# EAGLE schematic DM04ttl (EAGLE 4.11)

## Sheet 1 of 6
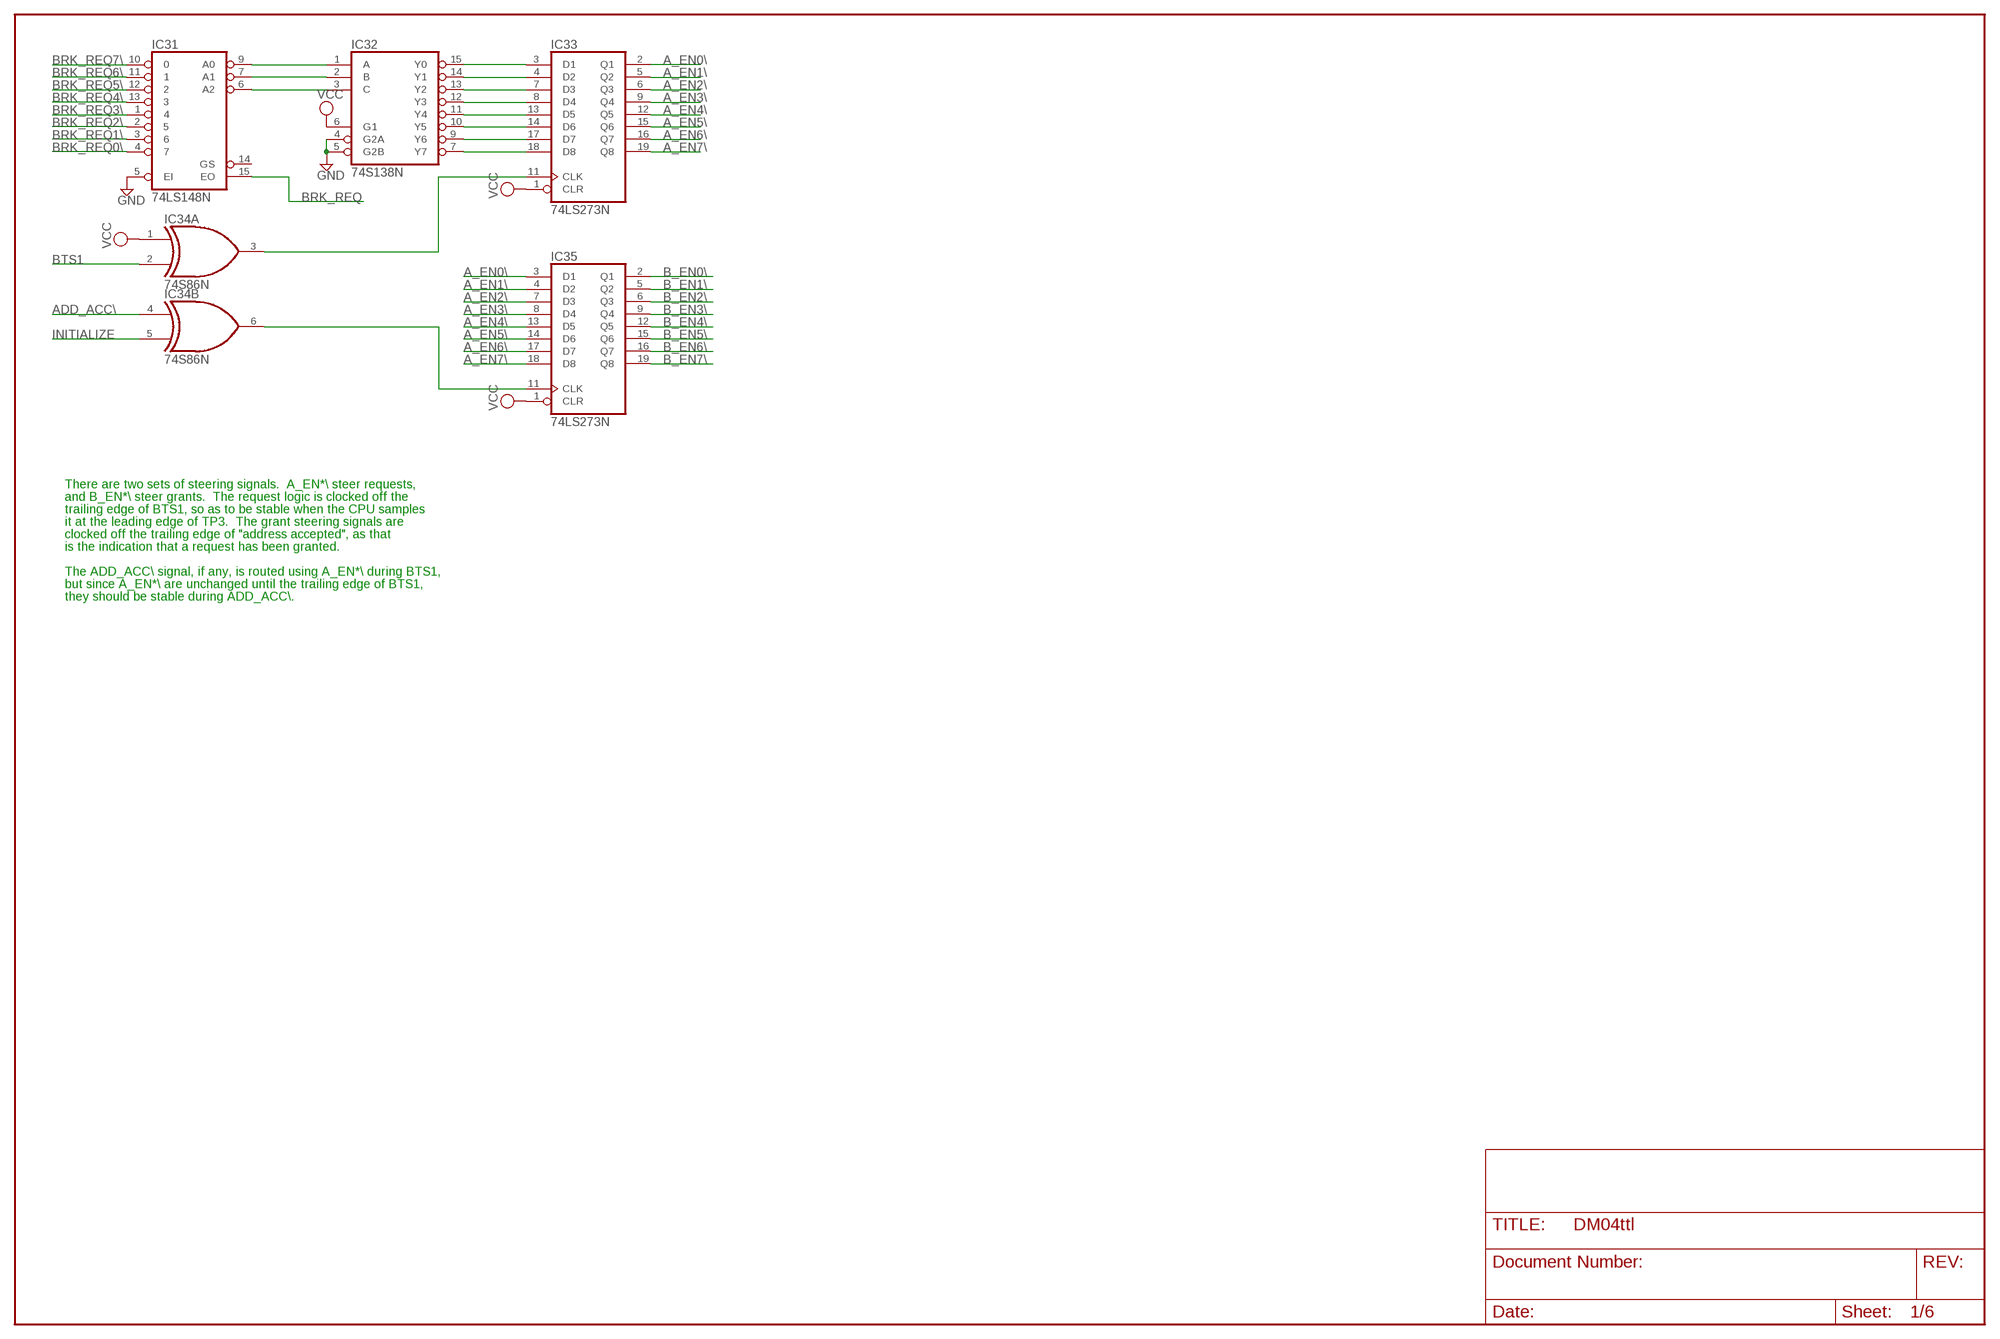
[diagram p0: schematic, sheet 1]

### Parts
IC31  74LS148N  [DIL16]
IC32  74S138N  [DIL16]
IC33  74LS273N  [DIL20]
IC34  74S86N  [DIL14]
IC35  74LS273N  [DIL20]

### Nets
A_EN0\: IC33.2(Q1) IC35.3(D1) ; also sheet 4,6
A_EN1\: IC33.5(Q2) IC35.4(D2) ; also sheet 4,6
A_EN2\: IC33.6(Q3) IC35.7(D3) ; also sheet 4,6
A_EN3\: IC33.9(Q4) IC35.8(D4) ; also sheet 4,6
A_EN4\: IC33.12(Q5) IC35.13(D5) ; also sheet 3
A_EN5\: IC33.15(Q6) IC35.14(D6) ; also sheet 3
A_EN6\: IC33.16(Q7) IC35.17(D7) ; also sheet 3
A_EN7\: IC33.19(Q8) IC35.18(D8) ; also sheet 3
ADD_ACC\: IC34.4(B:I0) ; also sheet 3,6
B_EN0\: IC35.2(Q1) ; also sheet 5,6
B_EN1\: IC35.5(Q2) ; also sheet 5,6
B_EN2\: IC35.6(Q3) ; also sheet 5,6
B_EN3\: IC35.9(Q4) ; also sheet 5,6
B_EN4\: IC35.12(Q5) ; also sheet 3
B_EN5\: IC35.15(Q6) ; also sheet 3
B_EN6\: IC35.16(Q7) ; also sheet 3
B_EN7\: IC35.19(Q8) ; also sheet 3
BRK_REQ: IC31.15(EO) ; also sheet 5
BRK_REQ0\: IC31.4 ; also sheet 3
BRK_REQ1\: IC31.3 ; also sheet 3
BRK_REQ2\: IC31.2 ; also sheet 3
BRK_REQ3\: IC31.1 ; also sheet 3
BRK_REQ4\: IC31.13 ; also sheet 3
BRK_REQ5\: IC31.12 ; also sheet 3
BRK_REQ6\: IC31.11 ; also sheet 3
BRK_REQ7\: IC31.10 ; also sheet 3
BTS1: IC34.2(A:I1) ; also sheet 2
GND [Supply]: IC31.5(EI) IC32.4(G2A) IC32.5(G2B) ; also sheet 2,3,4,5,6
INITIALIZE: IC34.5(B:I1) ; also sheet 3
N$2: IC31.6(A2) IC32.3(C)
N$3: IC34.6(B:O) IC35.11(CLK)
N$6: IC31.7(A1) IC32.2(B)
N$8: IC31.9(A0) IC32.1(A)
N$12: IC32.15(Y0) IC33.3(D1)
N$14: IC32.7(Y7) IC33.18(D8)
N$16: IC32.9(Y6) IC33.17(D7)
N$18: IC32.10(Y5) IC33.14(D6)
N$20: IC32.11(Y4) IC33.13(D5)
N$22: IC32.12(Y3) IC33.8(D4)
N$24: IC32.13(Y2) IC33.7(D3)
N$26: IC32.14(Y1) IC33.4(D2)
N$27: IC33.11(CLK) IC34.3(A:O)
VCC [Supply]: IC32.6(G1) IC33.1(CLR) IC34.1(A:I0) IC35.1(CLR) ; also sheet 2,3
Unconnected: IC31.14(GS) IC34.8(C:O) IC34.9(C:I0) IC34.10(C:I1) IC34.11(D:O) IC34.12(D:I0) IC34.13(D:I1)

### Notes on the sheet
- There are two sets of steering signals.  A_EN*\ steer requests,
- and B_EN*\ steer grants.  The request logic is clocked off the
- trailing edge of BTS1, so as to be stable when the CPU samples
- it at the leading edge of TP3.  The grant steering signals are
- clocked off the trailing edge of "address accepted", as that
- is the indication that a request has been granted.
- The ADD_ACC\ signal, if any, is routed using A_EN*\ during BTS1,
- but since A_EN*\ are unchanged until the trailing edge of BTS1,
- they should be stable during ADD_ACC\.

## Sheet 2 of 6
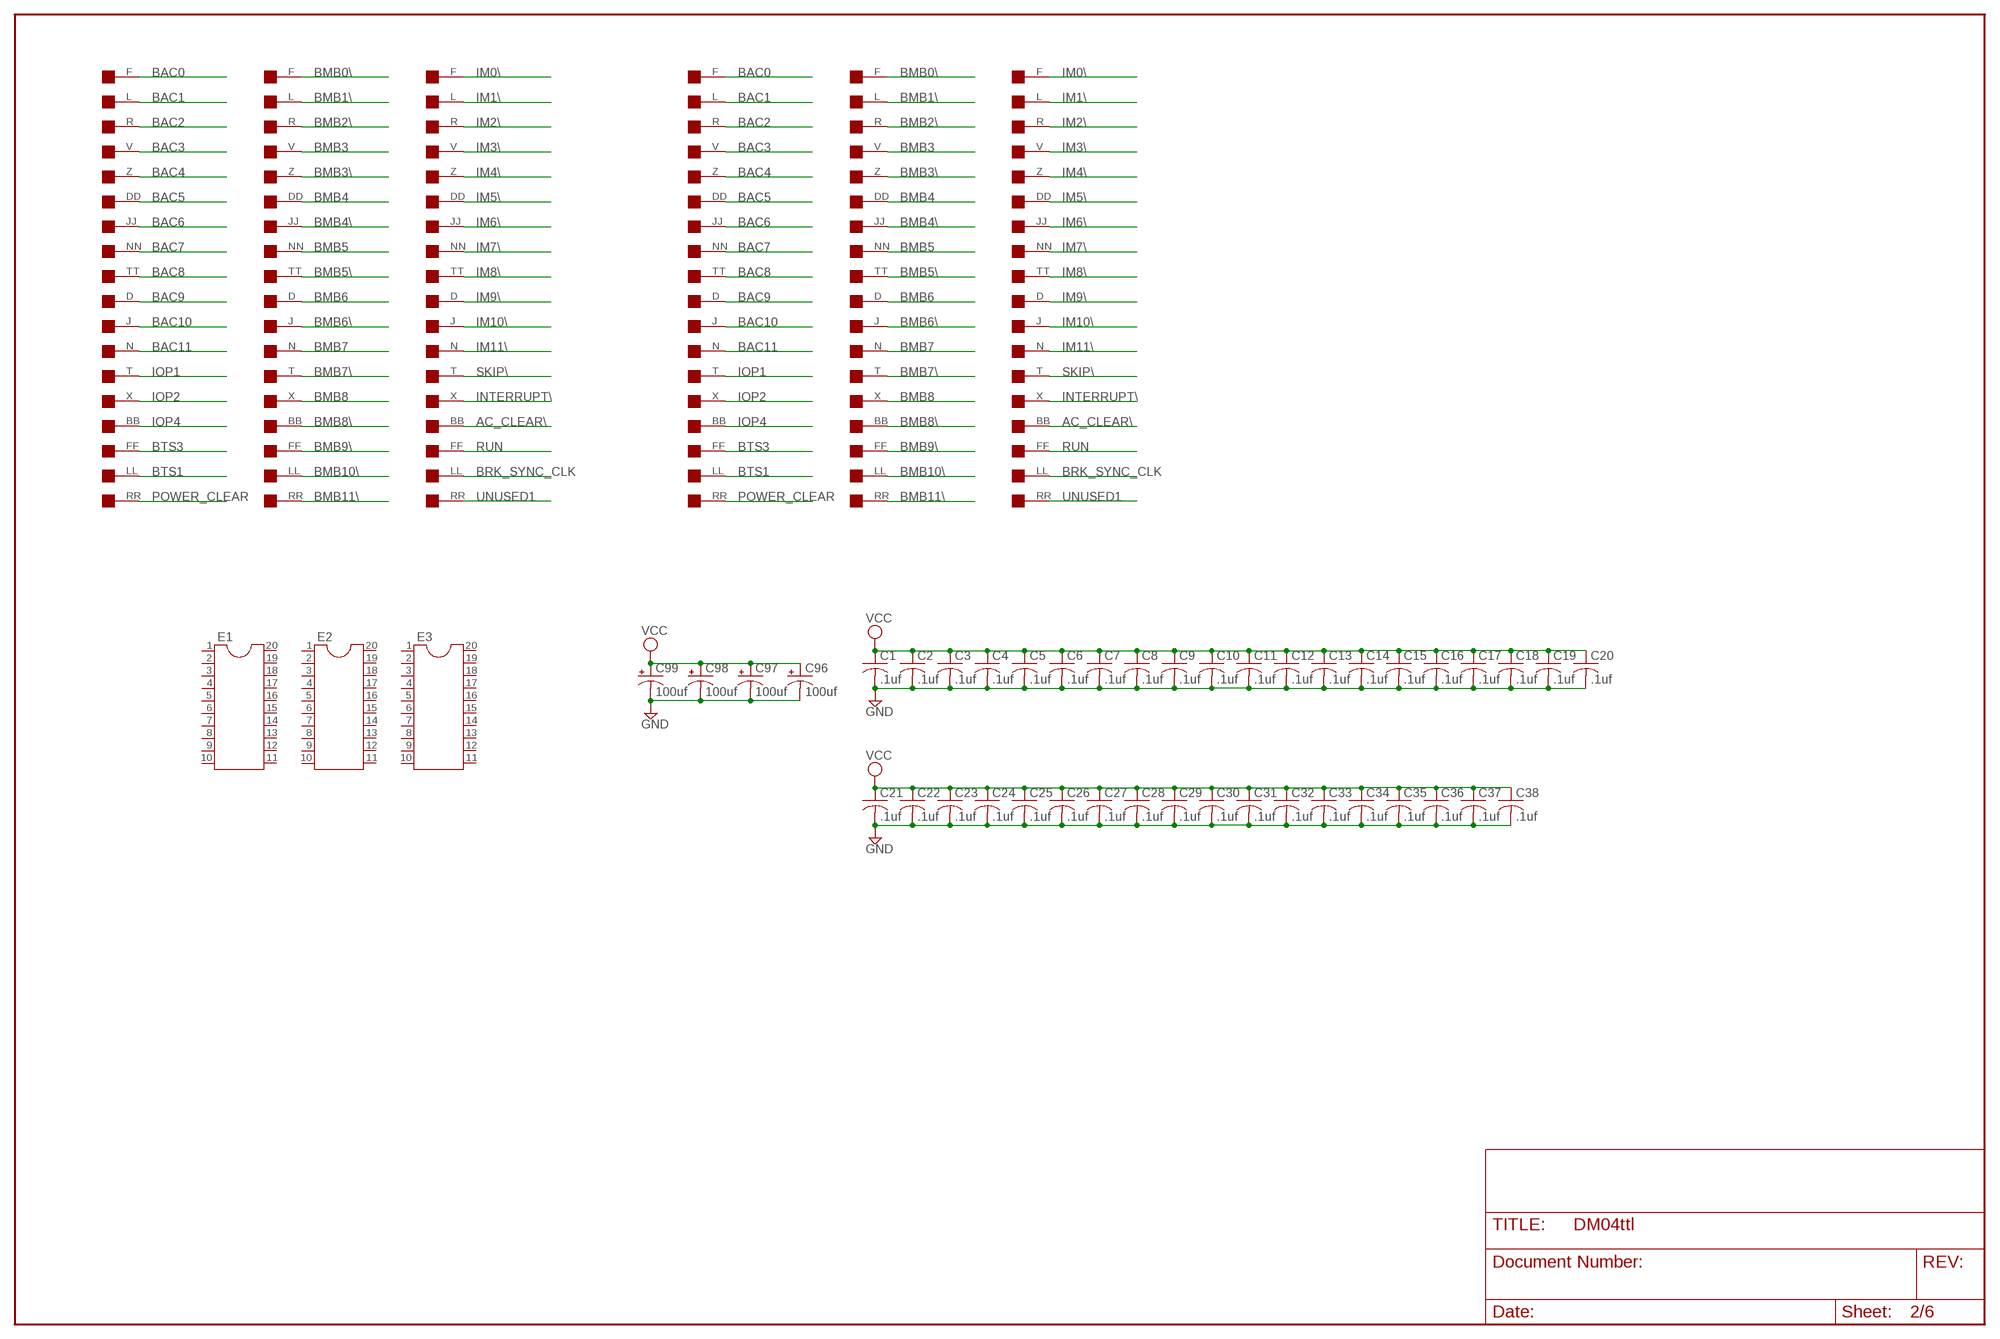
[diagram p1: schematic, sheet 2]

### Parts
AC0  BC08J  [DEC40PINV]
AC1  BC08J  [DEC40PINV]
BAC0  BC08J  [DEC40PINV]
BAC1  BC08J  [DEC40PINV]
BMB0  BC08J  [DEC40PINV]
BMB1  BC08J  [DEC40PINV]
C1  .1uf  C-US050-025X075  [C050-025X075]
C2  .1uf  C-US050-025X075  [C050-025X075]
C3  .1uf  C-US050-025X075  [C050-025X075]
C4  .1uf  C-US050-025X075  [C050-025X075]
C5  .1uf  C-US050-025X075  [C050-025X075]
C6  .1uf  C-US050-025X075  [C050-025X075]
C7  .1uf  C-US050-025X075  [C050-025X075]
C8  .1uf  C-US050-025X075  [C050-025X075]
C9  .1uf  C-US050-025X075  [C050-025X075]
C10  .1uf  C-US050-025X075  [C050-025X075]
C11  .1uf  C-US050-025X075  [C050-025X075]
C12  .1uf  C-US050-025X075  [C050-025X075]
C13  .1uf  C-US050-025X075  [C050-025X075]
C14  .1uf  C-US050-025X075  [C050-025X075]
C15  .1uf  C-US050-025X075  [C050-025X075]
C16  .1uf  C-US050-025X075  [C050-025X075]
C17  .1uf  C-US050-025X075  [C050-025X075]
C18  .1uf  C-US050-025X075  [C050-025X075]
C19  .1uf  C-US050-025X075  [C050-025X075]
C20  .1uf  C-US050-025X075  [C050-025X075]
C21  .1uf  C-US050-025X075  [C050-025X075]
C22  .1uf  C-US050-025X075  [C050-025X075]
C23  .1uf  C-US050-025X075  [C050-025X075]
C24  .1uf  C-US050-025X075  [C050-025X075]
C25  .1uf  C-US050-025X075  [C050-025X075]
C26  .1uf  C-US050-025X075  [C050-025X075]
C27  .1uf  C-US050-025X075  [C050-025X075]
C28  .1uf  C-US050-025X075  [C050-025X075]
C29  .1uf  C-US050-025X075  [C050-025X075]
C30  .1uf  C-US050-025X075  [C050-025X075]
C31  .1uf  C-US050-025X075  [C050-025X075]
C32  .1uf  C-US050-025X075  [C050-025X075]
C33  .1uf  C-US050-025X075  [C050-025X075]
C34  .1uf  C-US050-025X075  [C050-025X075]
C35  .1uf  C-US050-025X075  [C050-025X075]
C36  .1uf  C-US050-025X075  [C050-025X075]
C37  .1uf  C-US050-025X075  [C050-025X075]
C38  .1uf  C-US050-025X075  [C050-025X075]
C96  100uf  CPOL-USE22-6AXIAL  [E22-6]
C97  100uf  CPOL-USE22-6AXIAL  [E22-6]
C98  100uf  CPOL-USE22-6AXIAL  [E22-6]
C99  100uf  CPOL-USE22-6AXIAL  [E22-6]
E1  DIL20  [DIL20]
E2  DIL20  [DIL20]
E3  DIL20  [DIL20]

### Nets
AC_CLEAR\: AC0.BB AC1.BB
BAC0: BAC0.F BAC1.F
BAC1: BAC0.L BAC1.L
BAC2: BAC0.R BAC1.R
BAC3: BAC0.V BAC1.V
BAC4: BAC0.Z BAC1.Z
BAC5: BAC0.DD BAC1.DD
BAC6: BAC0.JJ BAC1.JJ
BAC7: BAC0.NN BAC1.NN
BAC8: BAC0.TT BAC1.TT
BAC9: BAC0.D BAC1.D
BAC10: BAC0.J BAC1.J
BAC11: BAC0.N BAC1.N
BMB0\: BMB0.F BMB1.F
BMB1\: BMB0.L BMB1.L
BMB2\: BMB0.R BMB1.R
BMB3: BMB0.V BMB1.V
BMB3\: BMB0.Z BMB1.Z
BMB4: BMB0.DD BMB1.DD
BMB4\: BMB0.JJ BMB1.JJ
BMB5: BMB0.NN BMB1.NN
BMB5\: BMB0.TT BMB1.TT
BMB6: BMB0.D BMB1.D
BMB6\: BMB0.J BMB1.J
BMB7: BMB0.N BMB1.N
BMB7\: BMB0.T BMB1.T
BMB8: BMB0.X BMB1.X
BMB8\: BMB0.BB BMB1.BB
BMB9\: BMB0.FF BMB1.FF
BMB10\: BMB0.LL BMB1.LL
BMB11\: BMB0.RR BMB1.RR
BRK_SYNC_CLK: AC0.LL AC1.LL
BTS1: BAC0.LL BAC1.LL ; also sheet 1
BTS3: BAC0.FF BAC1.FF
GND [Supply]: C1.2 C2.2 C3.2 C4.2 C5.2 C6.2 C7.2 C8.2 C9.2 C10.2 C11.2 C12.2 C13.2 C14.2 C15.2 C16.2 C17.2 C18.2 C19.2 C20.2 C21.2 C22.2 C23.2 C24.2 C25.2 C26.2 C27.2 C28.2 C29.2 C30.2 C31.2 C32.2 C33.2 C34.2 C35.2 C36.2 C37.2 C38.2 C96.- C97.- C98.- C99.- ; also sheet 1,3,4,5,6
IM0\: AC0.F AC1.F
IM1\: AC0.L AC1.L
IM2\: AC0.R AC1.R
IM3\: AC0.V AC1.V
IM4\: AC0.Z AC1.Z
IM5\: AC0.DD AC1.DD
IM6\: AC0.JJ AC1.JJ
IM7\: AC0.NN AC1.NN
IM8\: AC0.TT AC1.TT
IM9\: AC0.D AC1.D
IM10\: AC0.J AC1.J
IM11\: AC0.N AC1.N
INTERRUPT\: AC0.X AC1.X
IOP1: BAC0.T BAC1.T
IOP2: BAC0.X BAC1.X
IOP4: BAC0.BB BAC1.BB
POWER_CLEAR: BAC0.RR BAC1.RR
RUN: AC0.FF AC1.FF
SKIP\: AC0.T AC1.T
UNUSED1: AC0.RR AC1.RR
VCC [Supply]: C1.1 C2.1 C3.1 C4.1 C5.1 C6.1 C7.1 C8.1 C9.1 C10.1 C11.1 C12.1 C13.1 C14.1 C15.1 C16.1 C17.1 C18.1 C19.1 C20.1 C21.1 C22.1 C23.1 C24.1 C25.1 C26.1 C27.1 C28.1 C29.1 C30.1 C31.1 C32.1 C33.1 C34.1 C35.1 C36.1 C37.1 C38.1 C96.+ C97.+ C98.+ C99.+ ; also sheet 1,3
Unconnected: E1.1 E1.2 E1.3 E1.4 E1.5 E1.6 E1.7 E1.8 E1.9 E1.10 E1.11 E1.12 E1.13 E1.14 E1.15 E1.16 E1.17 E1.18 E1.19 E1.20 E2.1 E2.2 E2.3 E2.4 E2.5 E2.6 E2.7 E2.8 E2.9 E2.10 E2.11 E2.12 E2.13 E2.14 E2.15 E2.16 E2.17 E2.18 E2.19 E2.20 E3.1 E3.2 E3.3 E3.4 E3.5 E3.6 E3.7 E3.8 E3.9 E3.10 E3.11 E3.12 E3.13 E3.14 E3.15 E3.16 E3.17 E3.18 E3.19 E3.20

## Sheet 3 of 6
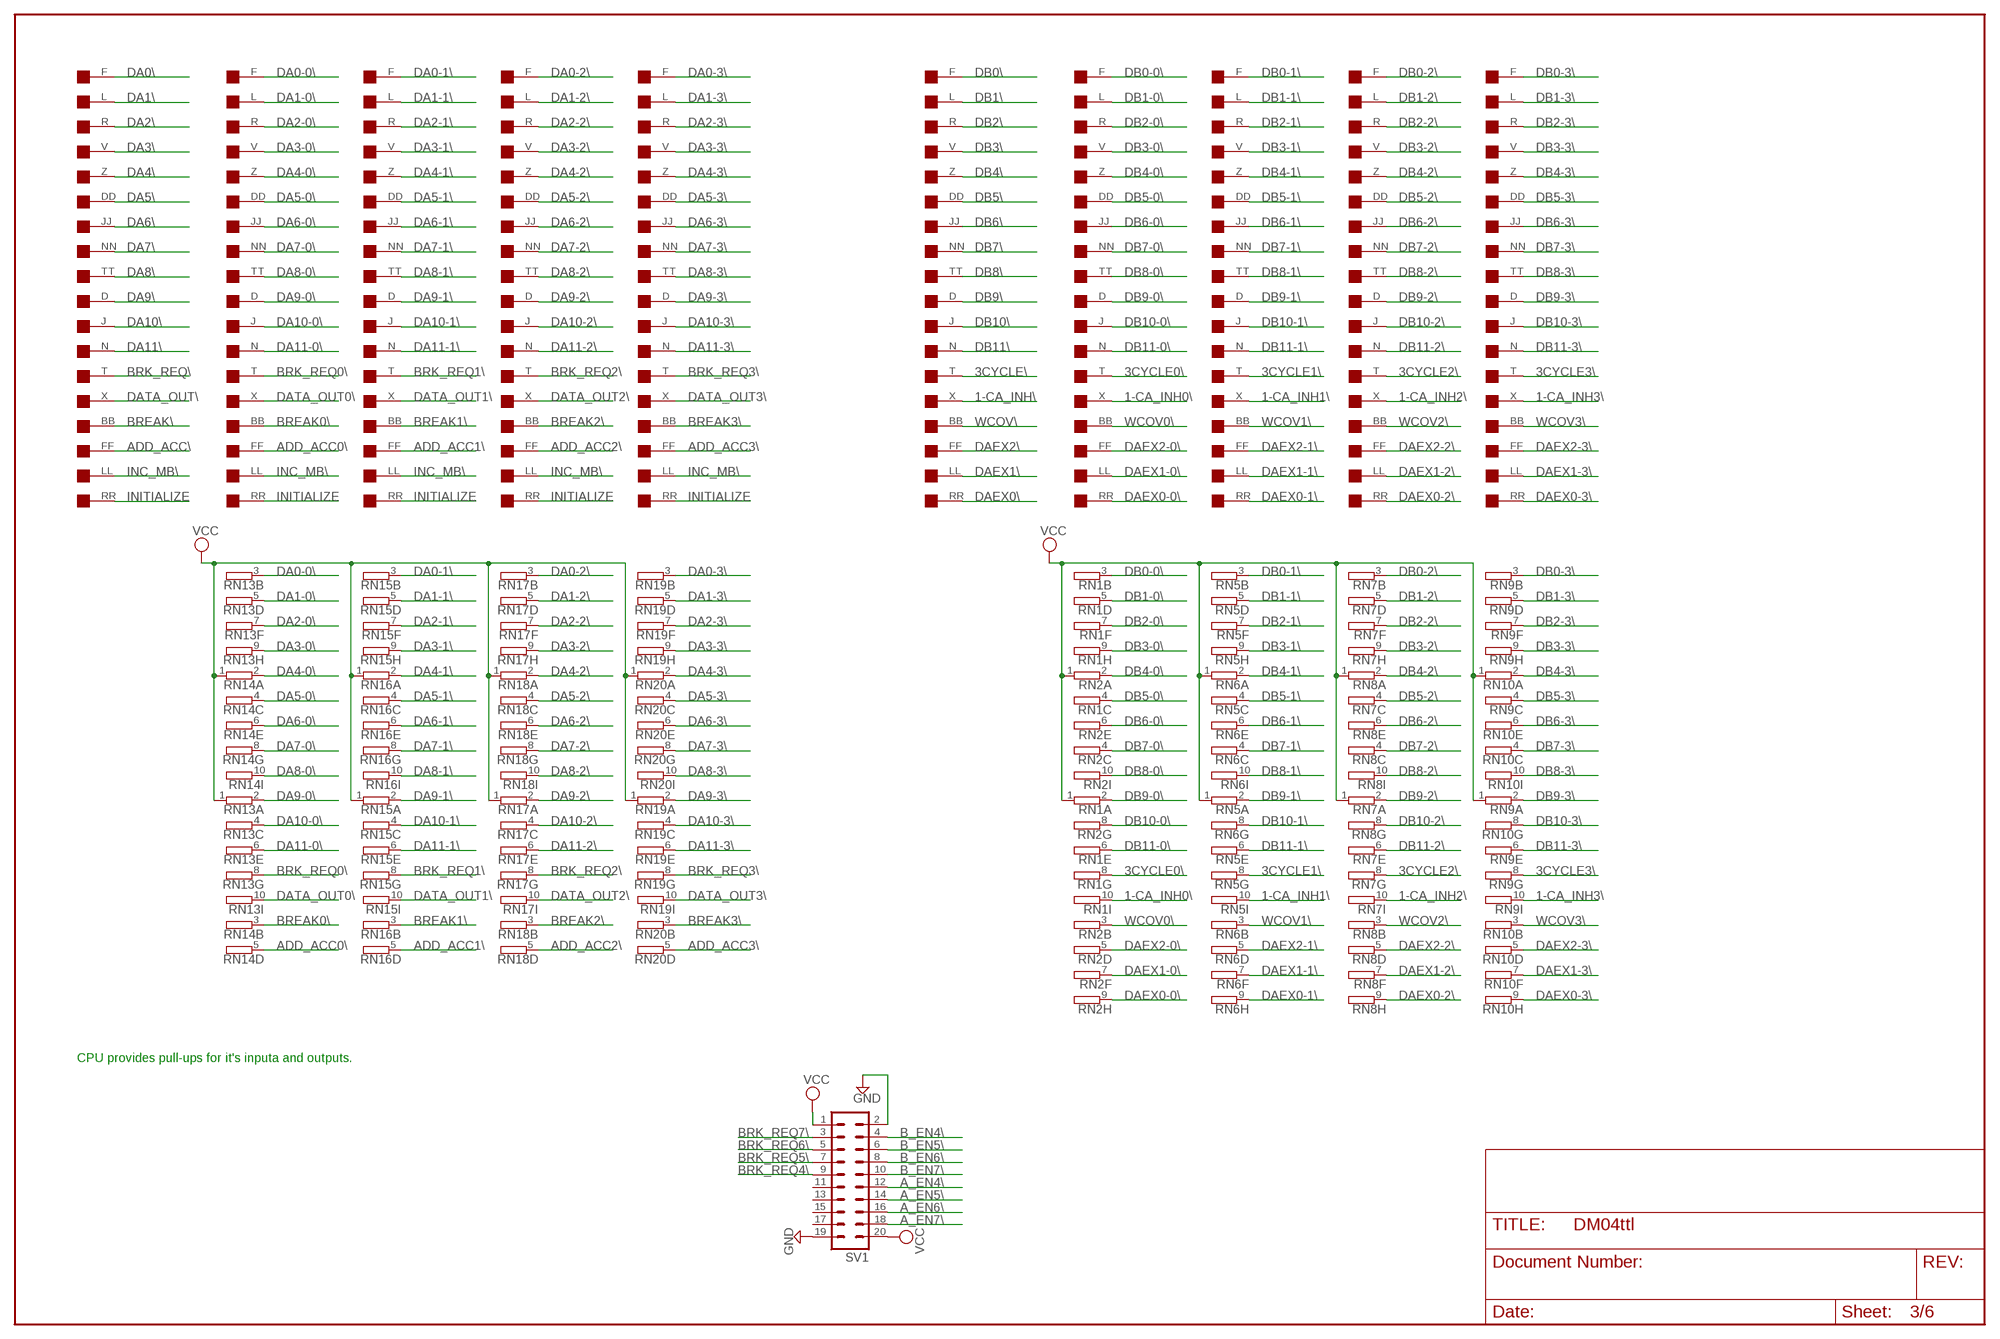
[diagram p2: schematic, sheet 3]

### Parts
ADDRESS  BC08J  [DEC40PINV]
ADDRESS0  BC08J  [DEC40PINV]
ADDRESS1  BC08J  [DEC40PINV]
ADDRESS2  BC08J  [DEC40PINV]
ADDRESS3  BC08J  [DEC40PINV]
DATA  BC08J  [DEC40PINV]
DATA0  BC08J  [DEC40PINV]
DATA1  BC08J  [DEC40PINV]
DATA2  BC08J  [DEC40PINV]
DATA3  BC08J  [DEC40PINV]
RN1  GE09R  [SIL10]
RN2  GE09R  [SIL10]
RN5  GE09R  [SIL10]
RN6  GE09R  [SIL10]
RN7  GE09R  [SIL10]
RN8  GE09R  [SIL10]
RN9  GE09R  [SIL10]
RN10  GE09R  [SIL10]
RN13  GE09R  [SIL10]
RN14  GE09R  [SIL10]
RN15  GE09R  [SIL10]
RN16  GE09R  [SIL10]
RN17  GE09R  [SIL10]
RN18  GE09R  [SIL10]
RN19  GE09R  [SIL10]
RN20  GE09R  [SIL10]
SV1  MA10-2  [MA10-2]

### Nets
1-CA_INH0\: DATA0.X RN1.10 ; also sheet 5
1-CA_INH1\: DATA1.X RN5.10 ; also sheet 5
1-CA_INH2\: DATA2.X RN7.10 ; also sheet 5
1-CA_INH3\: DATA3.X RN9.10 ; also sheet 5
1-CA_INH\: DATA.X ; also sheet 5
3CYCLE0\: DATA0.T RN1.8 ; also sheet 4
3CYCLE1\: DATA1.T RN5.8 ; also sheet 4
3CYCLE2\: DATA2.T RN7.8 ; also sheet 4
3CYCLE3\: DATA3.T RN9.8 ; also sheet 4
3CYCLE\: DATA.T ; also sheet 4
A_EN4\: SV1.12 ; also sheet 1
A_EN5\: SV1.14 ; also sheet 1
A_EN6\: SV1.16 ; also sheet 1
A_EN7\: SV1.18 ; also sheet 1
ADD_ACC0\: ADDRESS0.FF RN14.5 ; also sheet 6
ADD_ACC1\: ADDRESS1.FF RN16.5 ; also sheet 6
ADD_ACC2\: ADDRESS2.FF RN18.5 ; also sheet 6
ADD_ACC3\: ADDRESS3.FF RN20.5 ; also sheet 6
ADD_ACC\: ADDRESS.FF ; also sheet 1,6
B_EN4\: SV1.4 ; also sheet 1
B_EN5\: SV1.6 ; also sheet 1
B_EN6\: SV1.8 ; also sheet 1
B_EN7\: SV1.10 ; also sheet 1
BREAK0\: ADDRESS0.BB RN14.3 ; also sheet 6
BREAK1\: ADDRESS1.BB RN16.3 ; also sheet 6
BREAK2\: ADDRESS2.BB RN18.3 ; also sheet 6
BREAK3\: ADDRESS3.BB RN20.3 ; also sheet 6
BREAK\: ADDRESS.BB ; also sheet 6
BRK_REQ0\: ADDRESS0.T RN13.8 ; also sheet 1
BRK_REQ1\: ADDRESS1.T RN15.8 ; also sheet 1
BRK_REQ2\: ADDRESS2.T RN17.8 ; also sheet 1
BRK_REQ3\: ADDRESS3.T RN19.8 ; also sheet 1
BRK_REQ4\: SV1.9 ; also sheet 1
BRK_REQ5\: SV1.7 ; also sheet 1
BRK_REQ6\: SV1.5 ; also sheet 1
BRK_REQ7\: SV1.3 ; also sheet 1
BRK_REQ\: ADDRESS.T ; also sheet 5
DA0-0\: ADDRESS0.F RN13.3 ; also sheet 4
DA0-1\: ADDRESS1.F RN15.3 ; also sheet 4
DA0-2\: ADDRESS2.F RN17.3 ; also sheet 4
DA0-3\: ADDRESS3.F RN19.3 ; also sheet 4
DA0\: ADDRESS.F ; also sheet 4
DA1-0\: ADDRESS0.L RN13.5 ; also sheet 4
DA1-1\: ADDRESS1.L RN15.5 ; also sheet 4
DA1-2\: ADDRESS2.L RN17.5 ; also sheet 4
DA1-3\: ADDRESS3.L RN19.5 ; also sheet 4
DA1\: ADDRESS.L ; also sheet 4
DA2-0\: ADDRESS0.R RN13.7 ; also sheet 4
DA2-1\: ADDRESS1.R RN15.7 ; also sheet 4
DA2-2\: ADDRESS2.R RN17.7 ; also sheet 4
DA2-3\: ADDRESS3.R RN19.7 ; also sheet 4
DA2\: ADDRESS.R ; also sheet 4
DA3-0\: ADDRESS0.V RN13.9 ; also sheet 4
DA3-1\: ADDRESS1.V RN15.9 ; also sheet 4
DA3-2\: ADDRESS2.V RN17.9 ; also sheet 4
DA3-3\: ADDRESS3.V RN19.9 ; also sheet 4
DA3\: ADDRESS.V ; also sheet 4
DA4-0\: ADDRESS0.Z RN14.2 ; also sheet 4
DA4-1\: ADDRESS1.Z RN16.2 ; also sheet 4
DA4-2\: ADDRESS2.Z RN18.2 ; also sheet 4
DA4-3\: ADDRESS3.Z RN20.2 ; also sheet 4
DA4\: ADDRESS.Z ; also sheet 4
DA5-0\: ADDRESS0.DD RN14.4 ; also sheet 4
DA5-1\: ADDRESS1.DD RN16.4 ; also sheet 4
DA5-2\: ADDRESS2.DD RN18.4 ; also sheet 4
DA5-3\: ADDRESS3.DD RN20.4 ; also sheet 4
DA5\: ADDRESS.DD ; also sheet 4
DA6-0\: ADDRESS0.JJ RN14.6 ; also sheet 4
DA6-1\: ADDRESS1.JJ RN16.6 ; also sheet 4
DA6-2\: ADDRESS2.JJ RN18.6 ; also sheet 4
DA6-3\: ADDRESS3.JJ RN20.6 ; also sheet 4
DA6\: ADDRESS.JJ ; also sheet 4
DA7-0\: ADDRESS0.NN RN14.8 ; also sheet 4
DA7-1\: ADDRESS1.NN RN16.8 ; also sheet 4
DA7-2\: ADDRESS2.NN RN18.8 ; also sheet 4
DA7-3\: ADDRESS3.NN RN20.8 ; also sheet 4
DA7\: ADDRESS.NN ; also sheet 4
DA8-0\: ADDRESS0.TT RN14.10 ; also sheet 4
DA8-1\: ADDRESS1.TT RN16.10 ; also sheet 4
DA8-2\: ADDRESS2.TT RN18.10 ; also sheet 4
DA8-3\: ADDRESS3.TT RN20.10 ; also sheet 4
DA8\: ADDRESS.TT ; also sheet 4
DA9-0\: ADDRESS0.D RN13.2 ; also sheet 4
DA9-1\: ADDRESS1.D RN15.2 ; also sheet 4
DA9-2\: ADDRESS2.D RN17.2 ; also sheet 4
DA9-3\: ADDRESS3.D RN19.2 ; also sheet 4
DA9\: ADDRESS.D ; also sheet 4
DA10-0\: ADDRESS0.J RN13.4 ; also sheet 4
DA10-1\: ADDRESS1.J RN15.4 ; also sheet 4
DA10-2\: ADDRESS2.J RN17.4 ; also sheet 4
DA10-3\: ADDRESS3.J RN19.4 ; also sheet 4
DA10\: ADDRESS.J ; also sheet 4
DA11-0\: ADDRESS0.N RN13.6 ; also sheet 4
DA11-1\: ADDRESS1.N RN15.6 ; also sheet 4
DA11-2\: ADDRESS2.N RN17.6 ; also sheet 4
DA11-3\: ADDRESS3.N RN19.6 ; also sheet 4
DA11\: ADDRESS.N ; also sheet 4
DAEX0-0\: DATA0.RR RN2.9 ; also sheet 4
DAEX0-1\: DATA1.RR RN6.9 ; also sheet 4
DAEX0-2\: DATA2.RR RN8.9 ; also sheet 4
DAEX0-3\: DATA3.RR RN10.9 ; also sheet 4
DAEX0\: DATA.RR ; also sheet 4
DAEX1-0\: DATA0.LL RN2.7 ; also sheet 4
DAEX1-1\: DATA1.LL RN6.7 ; also sheet 4
DAEX1-2\: DATA2.LL RN8.7 ; also sheet 4
DAEX1-3\: DATA3.LL RN10.7 ; also sheet 4
DAEX1\: DATA.LL ; also sheet 4
DAEX2-0\: DATA0.FF RN2.5 ; also sheet 4
DAEX2-1\: DATA1.FF RN6.5 ; also sheet 4
DAEX2-2\: DATA2.FF RN8.5 ; also sheet 4
DAEX2-3\: DATA3.FF RN10.5 ; also sheet 4
DAEX2\: DATA.FF ; also sheet 4
DATA_OUT0\: ADDRESS0.X RN13.10 ; also sheet 5
DATA_OUT1\: ADDRESS1.X RN15.10 ; also sheet 5
DATA_OUT2\: ADDRESS2.X RN17.10 ; also sheet 5
DATA_OUT3\: ADDRESS3.X RN19.10 ; also sheet 5
DATA_OUT\: ADDRESS.X ; also sheet 5
DB0-0\: DATA0.F RN1.3 ; also sheet 5
DB0-1\: DATA1.F RN5.3 ; also sheet 5
DB0-2\: DATA2.F RN7.3 ; also sheet 5
DB0-3\: DATA3.F RN9.3 ; also sheet 5
DB0\: DATA.F ; also sheet 5
DB1-0\: DATA0.L RN1.5 ; also sheet 5
DB1-1\: DATA1.L RN5.5 ; also sheet 5
DB1-2\: DATA2.L RN7.5 ; also sheet 5
DB1-3\: DATA3.L RN9.5 ; also sheet 5
DB1\: DATA.L ; also sheet 5
DB2-0\: DATA0.R RN1.7 ; also sheet 5
DB2-1\: DATA1.R RN5.7 ; also sheet 5
DB2-2\: DATA2.R RN7.7 ; also sheet 5
DB2-3\: DATA3.R RN9.7 ; also sheet 5
DB2\: DATA.R ; also sheet 5
DB3-0\: DATA0.V RN1.9 ; also sheet 5
DB3-1\: DATA1.V RN5.9 ; also sheet 5
DB3-2\: DATA2.V RN7.9 ; also sheet 5
DB3-3\: DATA3.V RN9.9 ; also sheet 5
DB3\: DATA.V ; also sheet 5
DB4-0\: DATA0.Z RN2.2 ; also sheet 5
DB4-1\: DATA1.Z RN6.2 ; also sheet 5
DB4-2\: DATA2.Z RN8.2 ; also sheet 5
DB4-3\: DATA3.Z RN10.2 ; also sheet 5
DB4\: DATA.Z ; also sheet 5
DB5-0\: DATA0.DD RN1.4 ; also sheet 5
DB5-1\: DATA1.DD RN5.4 ; also sheet 5
DB5-2\: DATA2.DD RN7.4 ; also sheet 5
DB5-3\: DATA3.DD RN9.4 ; also sheet 5
DB5\: DATA.DD ; also sheet 5
DB6-0\: DATA0.JJ RN2.6 ; also sheet 5
DB6-1\: DATA1.JJ RN6.6 ; also sheet 5
DB6-2\: DATA2.JJ RN8.6 ; also sheet 5
DB6-3\: DATA3.JJ RN10.6 ; also sheet 5
DB6\: DATA.JJ ; also sheet 5
DB7-0\: DATA0.NN RN2.4 ; also sheet 5
DB7-1\: DATA1.NN RN6.4 ; also sheet 5
DB7-2\: DATA2.NN RN8.4 ; also sheet 5
DB7-3\: DATA3.NN RN10.4 ; also sheet 5
DB7\: DATA.NN ; also sheet 5
DB8-0\: DATA0.TT RN2.10 ; also sheet 5
DB8-1\: DATA1.TT RN6.10 ; also sheet 5
DB8-2\: DATA2.TT RN8.10 ; also sheet 5
DB8-3\: DATA3.TT RN10.10 ; also sheet 5
DB8\: DATA.TT ; also sheet 5
DB9-0\: DATA0.D RN1.2 ; also sheet 5
DB9-1\: DATA1.D RN5.2 ; also sheet 5
DB9-2\: DATA2.D RN7.2 ; also sheet 5
DB9-3\: DATA3.D RN9.2 ; also sheet 5
DB9\: DATA.D ; also sheet 5
DB10-0\: DATA0.J RN2.8 ; also sheet 5
DB10-1\: DATA1.J RN6.8 ; also sheet 5
DB10-2\: DATA2.J RN8.8 ; also sheet 5
DB10-3\: DATA3.J RN10.8 ; also sheet 5
DB10\: DATA.J ; also sheet 5
DB11-0\: DATA0.N RN1.6 ; also sheet 5
DB11-1\: DATA1.N RN5.6 ; also sheet 5
DB11-2\: DATA2.N RN7.6 ; also sheet 5
DB11-3\: DATA3.N RN9.6 ; also sheet 5
DB11\: DATA.N ; also sheet 5
GND [Supply]: SV1.2 SV1.19 ; also sheet 1,2,4,5,6
INC_MB\: ADDRESS0.LL ADDRESS1.LL ADDRESS2.LL ADDRESS3.LL ADDRESS.LL
INITIALIZE: ADDRESS0.RR ADDRESS1.RR ADDRESS2.RR ADDRESS3.RR ADDRESS.RR ; also sheet 1
VCC [Supply]: RN1.1 RN2.1 RN5.1 RN6.1 RN7.1 RN8.1 RN9.1 RN10.1 RN13.1 RN14.1 RN15.1 RN16.1 RN17.1 RN18.1 RN19.1 RN20.1 SV1.1 SV1.20 ; also sheet 1,2
WCOV0\: DATA0.BB RN2.3 ; also sheet 6
WCOV1\: DATA1.BB RN6.3 ; also sheet 6
WCOV2\: DATA2.BB RN8.3 ; also sheet 6
WCOV3\: DATA3.BB RN10.3 ; also sheet 6
WCOV\: DATA.BB ; also sheet 6
Unconnected: RN14.7 RN14.9 RN16.7 RN16.9 RN18.7 RN18.9 RN20.7 RN20.9 SV1.11 SV1.13 SV1.15 SV1.17

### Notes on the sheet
- CPU provides pull-ups for it's inputa and outputs.

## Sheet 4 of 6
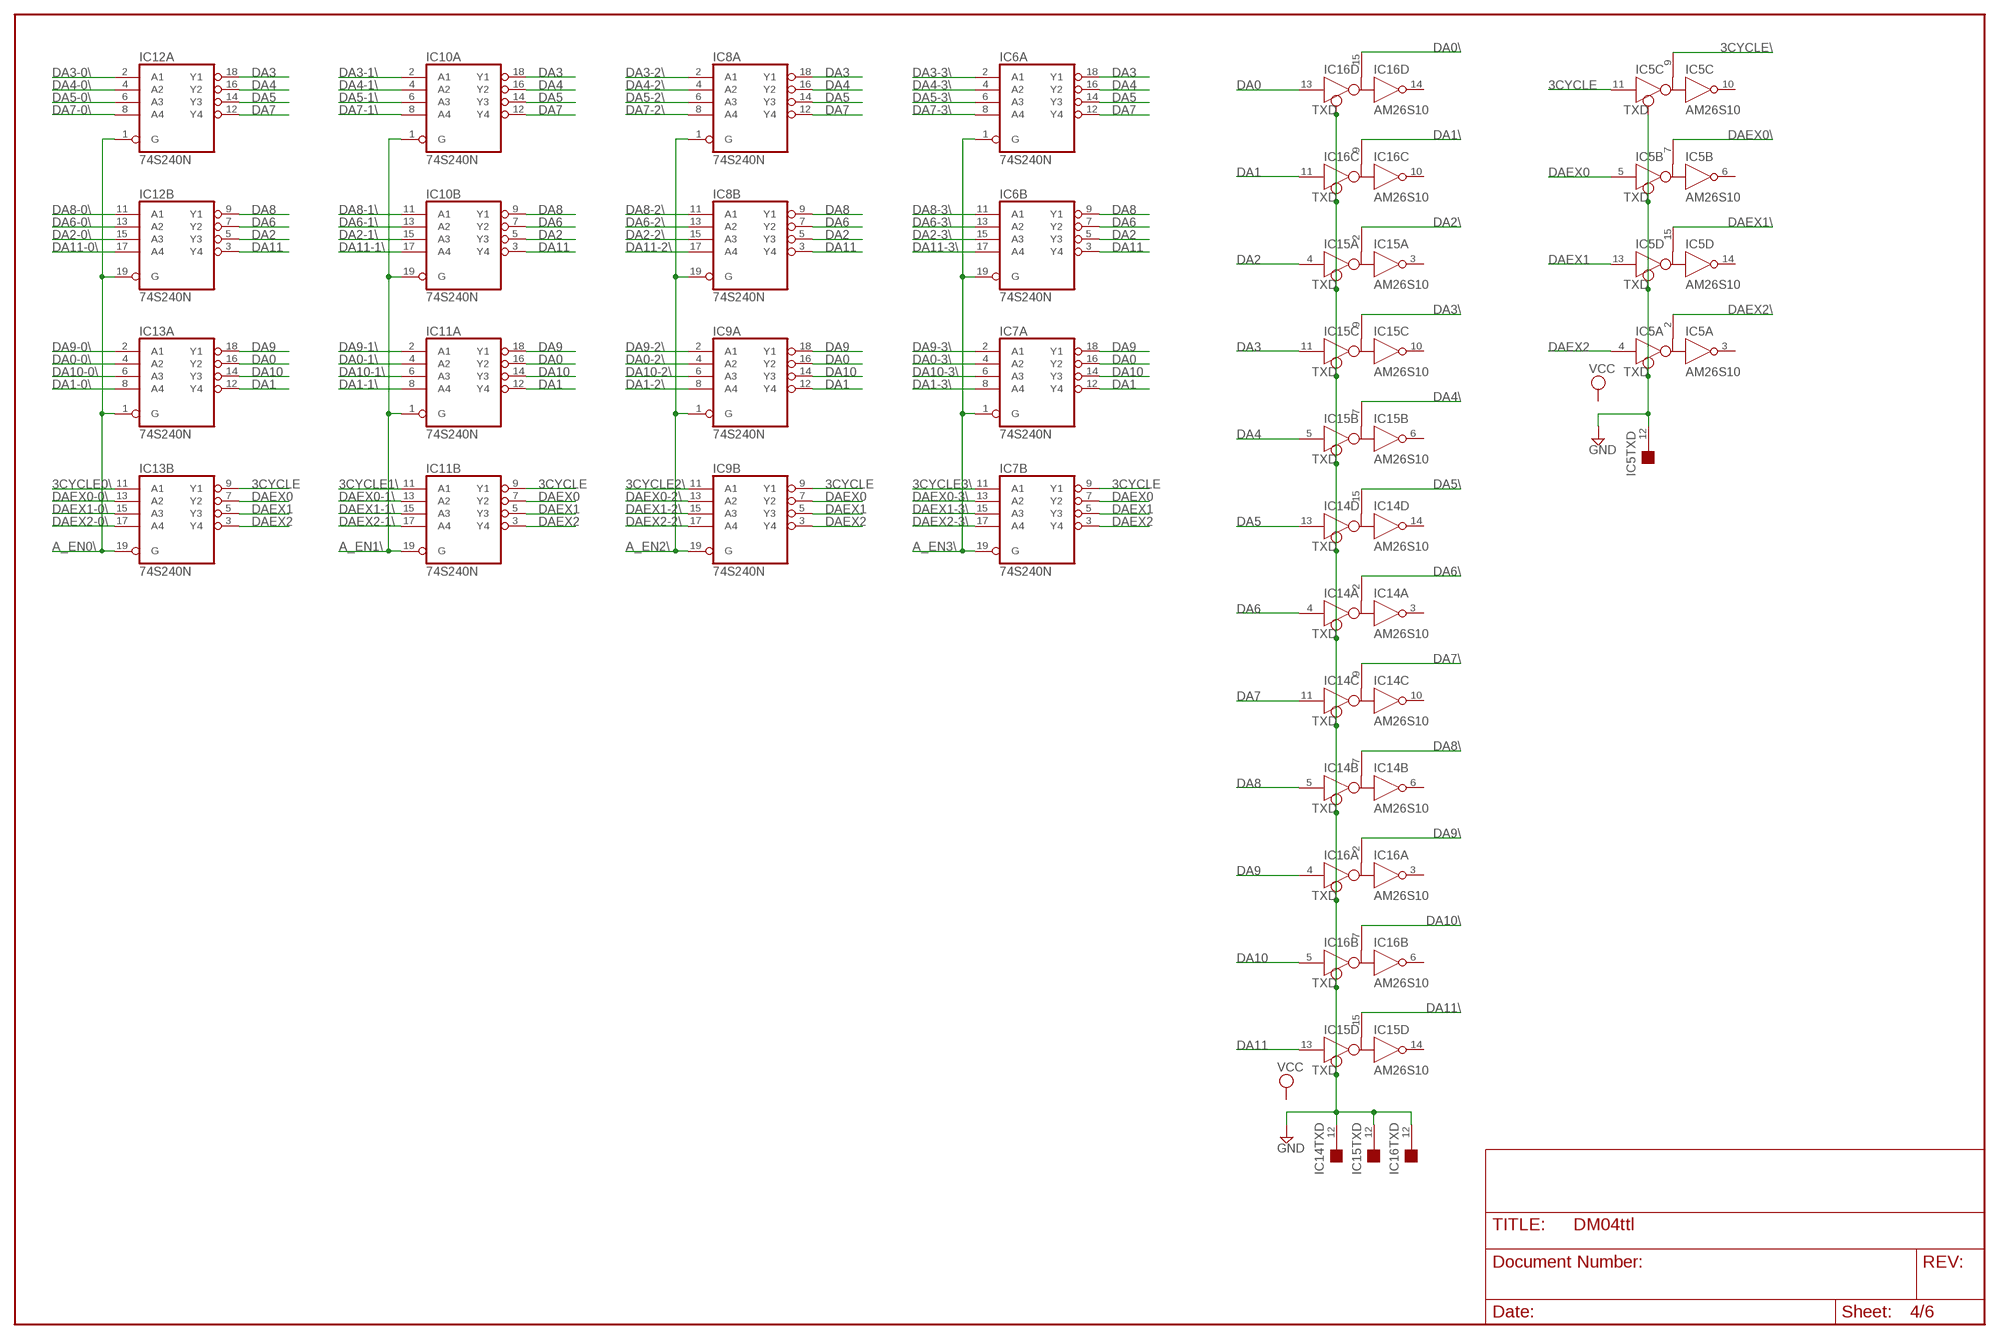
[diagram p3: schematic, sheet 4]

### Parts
IC5  AM26S10  [DIL16]
IC6  74S240N  [DIL20]
IC7  74S240N  [DIL20]
IC8  74S240N  [DIL20]
IC9  74S240N  [DIL20]
IC10  74S240N  [DIL20]
IC11  74S240N  [DIL20]
IC12  74S240N  [DIL20]
IC13  74S240N  [DIL20]
IC14  AM26S10  [DIL16]
IC15  AM26S10  [DIL16]
IC16  AM26S10  [DIL16]

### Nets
3CYCLE: IC5.11(C:D) IC7.9(B:Y1) IC9.9(B:Y1) IC11.9(B:Y1) IC13.9(B:Y1)
3CYCLE0\: IC13.11(B:A1) ; also sheet 3
3CYCLE1\: IC11.11(B:A1) ; also sheet 3
3CYCLE2\: IC9.11(B:A1) ; also sheet 3
3CYCLE3\: IC7.11(B:A1) ; also sheet 3
3CYCLE\: IC5.9(C:B) ; also sheet 3
A_EN0\: IC12.1(A:G) IC12.19(B:G) IC13.1(A:G) IC13.19(B:G) ; also sheet 1,6
A_EN1\: IC10.1(A:G) IC10.19(B:G) IC11.1(A:G) IC11.19(B:G) ; also sheet 1,6
A_EN2\: IC8.1(A:G) IC8.19(B:G) IC9.1(A:G) IC9.19(B:G) ; also sheet 1,6
A_EN3\: IC6.1(A:G) IC6.19(B:G) IC7.1(A:G) IC7.19(B:G) ; also sheet 1,6
DA0: IC7.16(A:Y2) IC9.16(A:Y2) IC11.16(A:Y2) IC13.16(A:Y2) IC16.13(D:D)
DA0-0\: IC13.4(A:A2) ; also sheet 3
DA0-1\: IC11.4(A:A2) ; also sheet 3
DA0-2\: IC9.4(A:A2) ; also sheet 3
DA0-3\: IC7.4(A:A2) ; also sheet 3
DA0\: IC16.15(D:B) ; also sheet 3
DA1: IC7.12(A:Y4) IC9.12(A:Y4) IC11.12(A:Y4) IC13.12(A:Y4) IC16.11(C:D)
DA1-0\: IC13.8(A:A4) ; also sheet 3
DA1-1\: IC11.8(A:A4) ; also sheet 3
DA1-2\: IC9.8(A:A4) ; also sheet 3
DA1-3\: IC7.8(A:A4) ; also sheet 3
DA1\: IC16.9(C:B) ; also sheet 3
DA2: IC6.5(B:Y3) IC8.5(B:Y3) IC10.5(B:Y3) IC12.5(B:Y3) IC15.4(A:D)
DA2-0\: IC12.15(B:A3) ; also sheet 3
DA2-1\: IC10.15(B:A3) ; also sheet 3
DA2-2\: IC8.15(B:A3) ; also sheet 3
DA2-3\: IC6.15(B:A3) ; also sheet 3
DA2\: IC15.2(A:B) ; also sheet 3
DA3: IC6.18(A:Y1) IC8.18(A:Y1) IC10.18(A:Y1) IC12.18(A:Y1) IC15.11(C:D)
DA3-0\: IC12.2(A:A1) ; also sheet 3
DA3-1\: IC10.2(A:A1) ; also sheet 3
DA3-2\: IC8.2(A:A1) ; also sheet 3
DA3-3\: IC6.2(A:A1) ; also sheet 3
DA3\: IC15.9(C:B) ; also sheet 3
DA4: IC6.16(A:Y2) IC8.16(A:Y2) IC10.16(A:Y2) IC12.16(A:Y2) IC15.5(B:D)
DA4-0\: IC12.4(A:A2) ; also sheet 3
DA4-1\: IC10.4(A:A2) ; also sheet 3
DA4-2\: IC8.4(A:A2) ; also sheet 3
DA4-3\: IC6.4(A:A2) ; also sheet 3
DA4\: IC15.7(B:B) ; also sheet 3
DA5: IC6.14(A:Y3) IC8.14(A:Y3) IC10.14(A:Y3) IC12.14(A:Y3) IC14.13(D:D)
DA5-0\: IC12.6(A:A3) ; also sheet 3
DA5-1\: IC10.6(A:A3) ; also sheet 3
DA5-2\: IC8.6(A:A3) ; also sheet 3
DA5-3\: IC6.6(A:A3) ; also sheet 3
DA5\: IC14.15(D:B) ; also sheet 3
DA6: IC6.7(B:Y2) IC8.7(B:Y2) IC10.7(B:Y2) IC12.7(B:Y2) IC14.4(A:D)
DA6-0\: IC12.13(B:A2) ; also sheet 3
DA6-1\: IC10.13(B:A2) ; also sheet 3
DA6-2\: IC8.13(B:A2) ; also sheet 3
DA6-3\: IC6.13(B:A2) ; also sheet 3
DA6\: IC14.2(A:B) ; also sheet 3
DA7: IC6.12(A:Y4) IC8.12(A:Y4) IC10.12(A:Y4) IC12.12(A:Y4) IC14.11(C:D)
DA7-0\: IC12.8(A:A4) ; also sheet 3
DA7-1\: IC10.8(A:A4) ; also sheet 3
DA7-2\: IC8.8(A:A4) ; also sheet 3
DA7-3\: IC6.8(A:A4) ; also sheet 3
DA7\: IC14.9(C:B) ; also sheet 3
DA8: IC6.9(B:Y1) IC8.9(B:Y1) IC10.9(B:Y1) IC12.9(B:Y1) IC14.5(B:D)
DA8-0\: IC12.11(B:A1) ; also sheet 3
DA8-1\: IC10.11(B:A1) ; also sheet 3
DA8-2\: IC8.11(B:A1) ; also sheet 3
DA8-3\: IC6.11(B:A1) ; also sheet 3
DA8\: IC14.7(B:B) ; also sheet 3
DA9: IC7.18(A:Y1) IC9.18(A:Y1) IC11.18(A:Y1) IC13.18(A:Y1) IC16.4(A:D)
DA9-0\: IC13.2(A:A1) ; also sheet 3
DA9-1\: IC11.2(A:A1) ; also sheet 3
DA9-2\: IC9.2(A:A1) ; also sheet 3
DA9-3\: IC7.2(A:A1) ; also sheet 3
DA9\: IC16.2(A:B) ; also sheet 3
DA10: IC7.14(A:Y3) IC9.14(A:Y3) IC11.14(A:Y3) IC13.14(A:Y3) IC16.5(B:D)
DA10-0\: IC13.6(A:A3) ; also sheet 3
DA10-1\: IC11.6(A:A3) ; also sheet 3
DA10-2\: IC9.6(A:A3) ; also sheet 3
DA10-3\: IC7.6(A:A3) ; also sheet 3
DA10\: IC16.7(B:B) ; also sheet 3
DA11: IC6.3(B:Y4) IC8.3(B:Y4) IC10.3(B:Y4) IC12.3(B:Y4) IC15.13(D:D)
DA11-0\: IC12.17(B:A4) ; also sheet 3
DA11-1\: IC10.17(B:A4) ; also sheet 3
DA11-2\: IC8.17(B:A4) ; also sheet 3
DA11-3\: IC6.17(B:A4) ; also sheet 3
DA11\: IC15.15(D:B) ; also sheet 3
DAEX0: IC5.5(B:D) IC7.7(B:Y2) IC9.7(B:Y2) IC11.7(B:Y2) IC13.7(B:Y2)
DAEX0-0\: IC13.13(B:A2) ; also sheet 3
DAEX0-1\: IC11.13(B:A2) ; also sheet 3
DAEX0-2\: IC9.13(B:A2) ; also sheet 3
DAEX0-3\: IC7.13(B:A2) ; also sheet 3
DAEX0\: IC5.7(B:B) ; also sheet 3
DAEX1: IC5.13(D:D) IC7.5(B:Y3) IC9.5(B:Y3) IC11.5(B:Y3) IC13.5(B:Y3)
DAEX1-0\: IC13.15(B:A3) ; also sheet 3
DAEX1-1\: IC11.15(B:A3) ; also sheet 3
DAEX1-2\: IC9.15(B:A3) ; also sheet 3
DAEX1-3\: IC7.15(B:A3) ; also sheet 3
DAEX1\: IC5.15(D:B) ; also sheet 3
DAEX2: IC5.4(A:D) IC7.3(B:Y4) IC9.3(B:Y4) IC11.3(B:Y4) IC13.3(B:Y4)
DAEX2-0\: IC13.17(B:A4) ; also sheet 3
DAEX2-1\: IC11.17(B:A4) ; also sheet 3
DAEX2-2\: IC9.17(B:A4) ; also sheet 3
DAEX2-3\: IC7.17(B:A4) ; also sheet 3
DAEX2\: IC5.2(A:B) ; also sheet 3
GND [Supply]: IC5.12(TXD:TXD) IC14.12(TXD:TXD) IC15.12(TXD:TXD) IC16.12(TXD:TXD) ; also sheet 1,2,3,5,6
Unconnected: IC5.3(A:R) IC5.6(B:R) IC5.10(C:R) IC5.14(D:R) IC14.3(A:R) IC14.6(B:R) IC14.10(C:R) IC14.14(D:R) IC15.3(A:R) IC15.6(B:R) IC15.10(C:R) IC15.14(D:R) IC16.3(A:R) IC16.6(B:R) IC16.10(C:R) IC16.14(D:R)

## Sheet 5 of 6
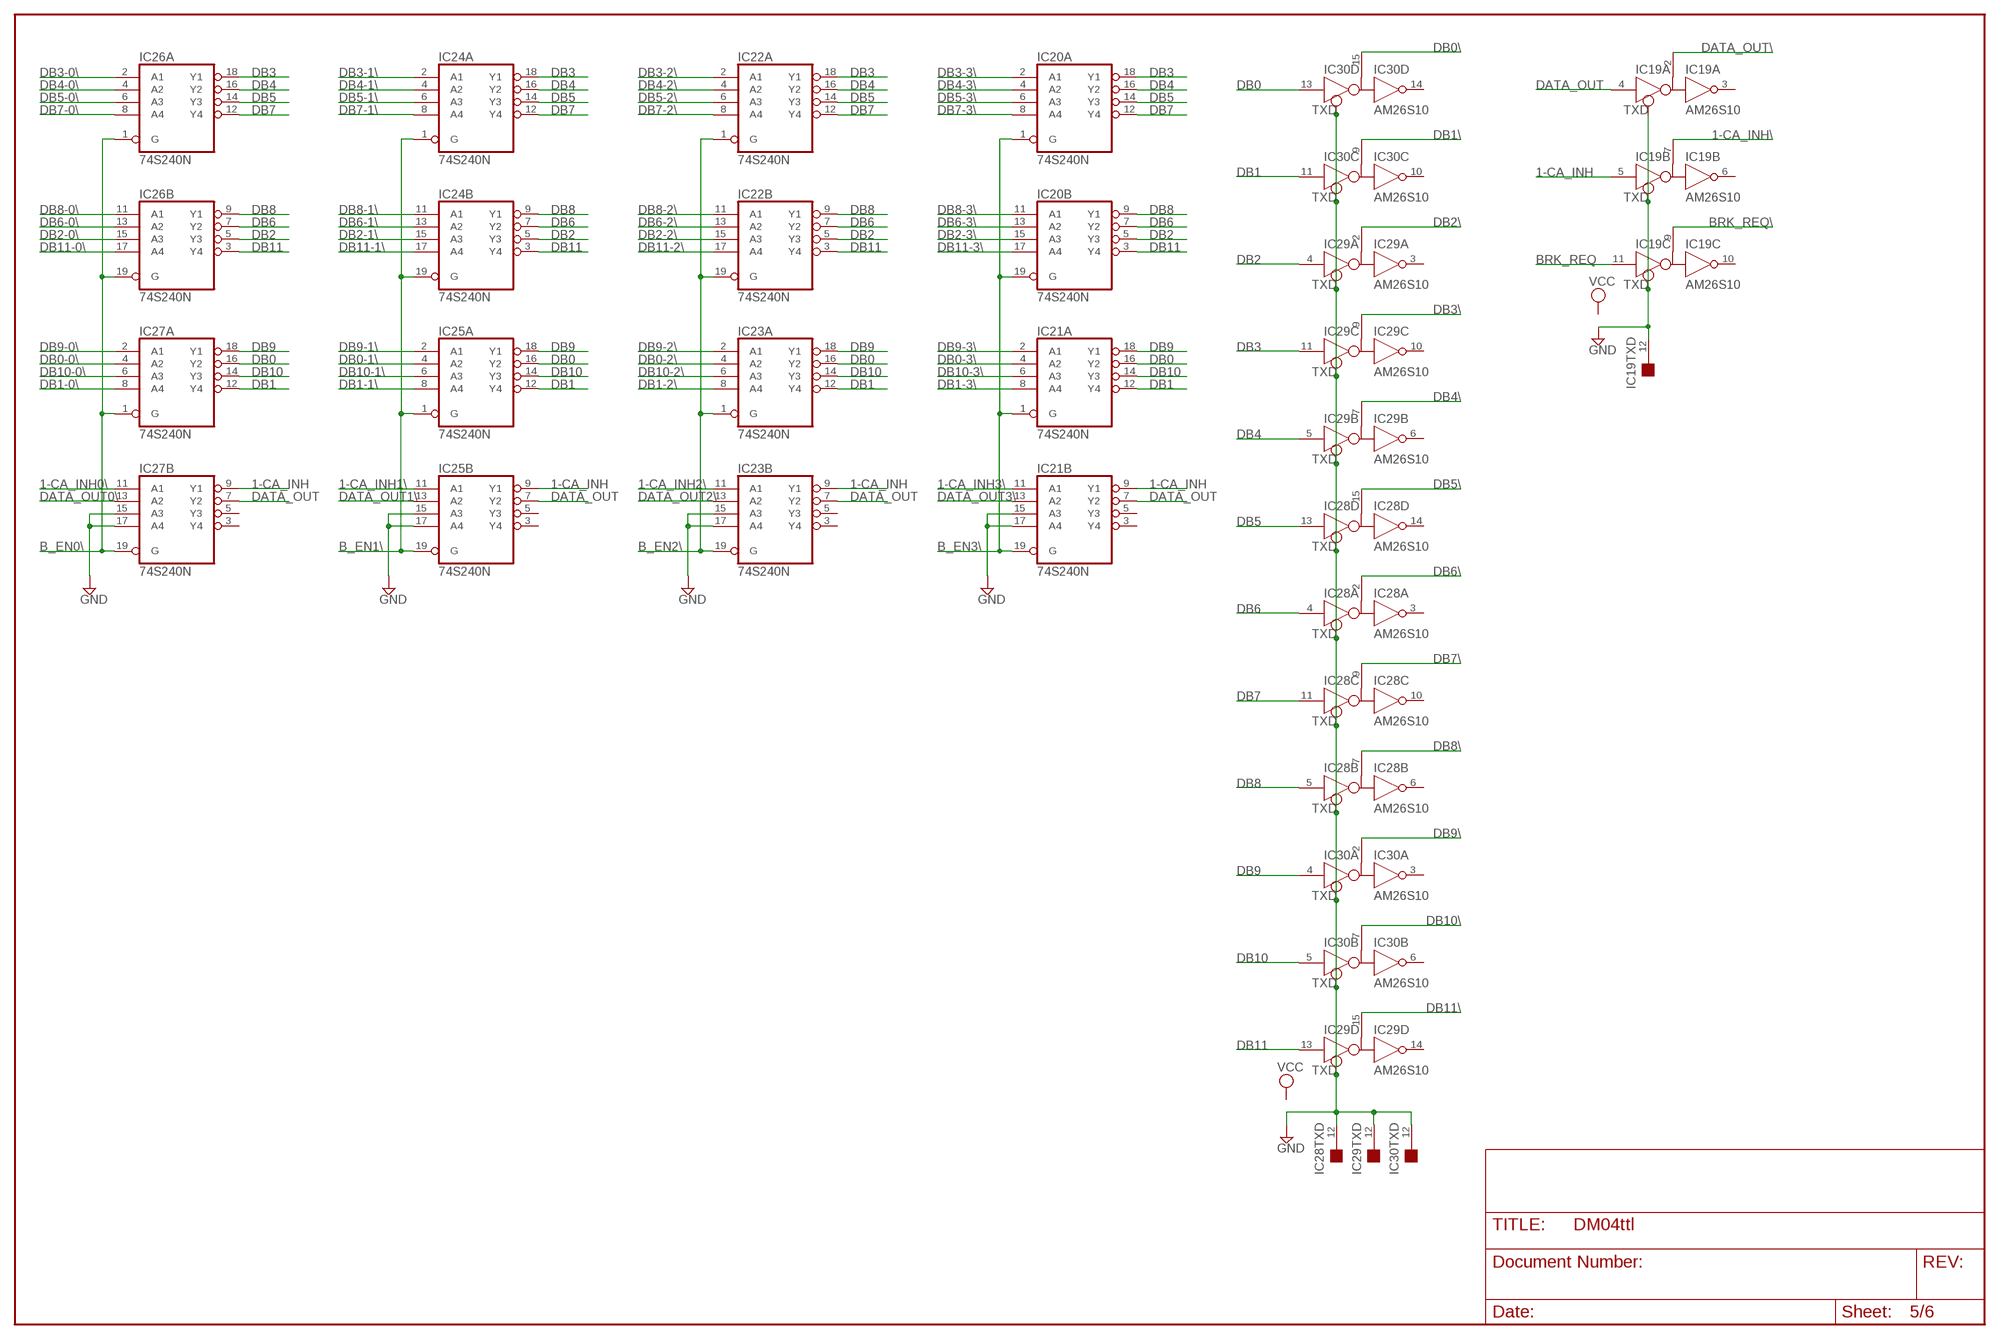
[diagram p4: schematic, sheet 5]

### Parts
IC19  AM26S10  [DIL16]
IC20  74S240N  [DIL20]
IC21  74S240N  [DIL20]
IC22  74S240N  [DIL20]
IC23  74S240N  [DIL20]
IC24  74S240N  [DIL20]
IC25  74S240N  [DIL20]
IC26  74S240N  [DIL20]
IC27  74S240N  [DIL20]
IC28  AM26S10  [DIL16]
IC29  AM26S10  [DIL16]
IC30  AM26S10  [DIL16]

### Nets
1-CA_INH: IC19.5(B:D) IC21.9(B:Y1) IC23.9(B:Y1) IC25.9(B:Y1) IC27.9(B:Y1)
1-CA_INH0\: IC27.11(B:A1) ; also sheet 3
1-CA_INH1\: IC25.11(B:A1) ; also sheet 3
1-CA_INH2\: IC23.11(B:A1) ; also sheet 3
1-CA_INH3\: IC21.11(B:A1) ; also sheet 3
1-CA_INH\: IC19.7(B:B) ; also sheet 3
B_EN0\: IC26.1(A:G) IC26.19(B:G) IC27.1(A:G) IC27.19(B:G) ; also sheet 1,6
B_EN1\: IC24.1(A:G) IC24.19(B:G) IC25.1(A:G) IC25.19(B:G) ; also sheet 1,6
B_EN2\: IC22.1(A:G) IC22.19(B:G) IC23.1(A:G) IC23.19(B:G) ; also sheet 1,6
B_EN3\: IC20.1(A:G) IC20.19(B:G) IC21.1(A:G) IC21.19(B:G) ; also sheet 1,6
BRK_REQ: IC19.11(C:D) ; also sheet 1
BRK_REQ\: IC19.9(C:B) ; also sheet 3
DATA_OUT: IC19.4(A:D) IC21.7(B:Y2) IC23.7(B:Y2) IC25.7(B:Y2) IC27.7(B:Y2)
DATA_OUT0\: IC27.13(B:A2) ; also sheet 3
DATA_OUT1\: IC25.13(B:A2) ; also sheet 3
DATA_OUT2\: IC23.13(B:A2) ; also sheet 3
DATA_OUT3\: IC21.13(B:A2) ; also sheet 3
DATA_OUT\: IC19.2(A:B) ; also sheet 3
DB0: IC21.16(A:Y2) IC23.16(A:Y2) IC25.16(A:Y2) IC27.16(A:Y2) IC30.13(D:D)
DB0-0\: IC27.4(A:A2) ; also sheet 3
DB0-1\: IC25.4(A:A2) ; also sheet 3
DB0-2\: IC23.4(A:A2) ; also sheet 3
DB0-3\: IC21.4(A:A2) ; also sheet 3
DB0\: IC30.15(D:B) ; also sheet 3
DB1: IC21.12(A:Y4) IC23.12(A:Y4) IC25.12(A:Y4) IC27.12(A:Y4) IC30.11(C:D)
DB1-0\: IC27.8(A:A4) ; also sheet 3
DB1-1\: IC25.8(A:A4) ; also sheet 3
DB1-2\: IC23.8(A:A4) ; also sheet 3
DB1-3\: IC21.8(A:A4) ; also sheet 3
DB1\: IC30.9(C:B) ; also sheet 3
DB2: IC20.5(B:Y3) IC22.5(B:Y3) IC24.5(B:Y3) IC26.5(B:Y3) IC29.4(A:D)
DB2-0\: IC26.15(B:A3) ; also sheet 3
DB2-1\: IC24.15(B:A3) ; also sheet 3
DB2-2\: IC22.15(B:A3) ; also sheet 3
DB2-3\: IC20.15(B:A3) ; also sheet 3
DB2\: IC29.2(A:B) ; also sheet 3
DB3: IC20.18(A:Y1) IC22.18(A:Y1) IC24.18(A:Y1) IC26.18(A:Y1) IC29.11(C:D)
DB3-0\: IC26.2(A:A1) ; also sheet 3
DB3-1\: IC24.2(A:A1) ; also sheet 3
DB3-2\: IC22.2(A:A1) ; also sheet 3
DB3-3\: IC20.2(A:A1) ; also sheet 3
DB3\: IC29.9(C:B) ; also sheet 3
DB4: IC20.16(A:Y2) IC22.16(A:Y2) IC24.16(A:Y2) IC26.16(A:Y2) IC29.5(B:D)
DB4-0\: IC26.4(A:A2) ; also sheet 3
DB4-1\: IC24.4(A:A2) ; also sheet 3
DB4-2\: IC22.4(A:A2) ; also sheet 3
DB4-3\: IC20.4(A:A2) ; also sheet 3
DB4\: IC29.7(B:B) ; also sheet 3
DB5: IC20.14(A:Y3) IC22.14(A:Y3) IC24.14(A:Y3) IC26.14(A:Y3) IC28.13(D:D)
DB5-0\: IC26.6(A:A3) ; also sheet 3
DB5-1\: IC24.6(A:A3) ; also sheet 3
DB5-2\: IC22.6(A:A3) ; also sheet 3
DB5-3\: IC20.6(A:A3) ; also sheet 3
DB5\: IC28.15(D:B) ; also sheet 3
DB6: IC20.7(B:Y2) IC22.7(B:Y2) IC24.7(B:Y2) IC26.7(B:Y2) IC28.4(A:D)
DB6-0\: IC26.13(B:A2) ; also sheet 3
DB6-1\: IC24.13(B:A2) ; also sheet 3
DB6-2\: IC22.13(B:A2) ; also sheet 3
DB6-3\: IC20.13(B:A2) ; also sheet 3
DB6\: IC28.2(A:B) ; also sheet 3
DB7: IC20.12(A:Y4) IC22.12(A:Y4) IC24.12(A:Y4) IC26.12(A:Y4) IC28.11(C:D)
DB7-0\: IC26.8(A:A4) ; also sheet 3
DB7-1\: IC24.8(A:A4) ; also sheet 3
DB7-2\: IC22.8(A:A4) ; also sheet 3
DB7-3\: IC20.8(A:A4) ; also sheet 3
DB7\: IC28.9(C:B) ; also sheet 3
DB8: IC20.9(B:Y1) IC22.9(B:Y1) IC24.9(B:Y1) IC26.9(B:Y1) IC28.5(B:D)
DB8-0\: IC26.11(B:A1) ; also sheet 3
DB8-1\: IC24.11(B:A1) ; also sheet 3
DB8-2\: IC22.11(B:A1) ; also sheet 3
DB8-3\: IC20.11(B:A1) ; also sheet 3
DB8\: IC28.7(B:B) ; also sheet 3
DB9: IC21.18(A:Y1) IC23.18(A:Y1) IC25.18(A:Y1) IC27.18(A:Y1) IC30.4(A:D)
DB9-0\: IC27.2(A:A1) ; also sheet 3
DB9-1\: IC25.2(A:A1) ; also sheet 3
DB9-2\: IC23.2(A:A1) ; also sheet 3
DB9-3\: IC21.2(A:A1) ; also sheet 3
DB9\: IC30.2(A:B) ; also sheet 3
DB10: IC21.14(A:Y3) IC23.14(A:Y3) IC25.14(A:Y3) IC27.14(A:Y3) IC30.5(B:D)
DB10-0\: IC27.6(A:A3) ; also sheet 3
DB10-1\: IC25.6(A:A3) ; also sheet 3
DB10-2\: IC23.6(A:A3) ; also sheet 3
DB10-3\: IC21.6(A:A3) ; also sheet 3
DB10\: IC30.7(B:B) ; also sheet 3
DB11: IC20.3(B:Y4) IC22.3(B:Y4) IC24.3(B:Y4) IC26.3(B:Y4) IC29.13(D:D)
DB11-0\: IC26.17(B:A4) ; also sheet 3
DB11-1\: IC24.17(B:A4) ; also sheet 3
DB11-2\: IC22.17(B:A4) ; also sheet 3
DB11-3\: IC20.17(B:A4) ; also sheet 3
DB11\: IC29.15(D:B) ; also sheet 3
GND [Supply]: IC19.12(TXD:TXD) IC21.15(B:A3) IC21.17(B:A4) IC23.15(B:A3) IC23.17(B:A4) IC25.15(B:A3) IC25.17(B:A4) IC27.15(B:A3) IC27.17(B:A4) IC28.12(TXD:TXD) IC29.12(TXD:TXD) IC30.12(TXD:TXD) ; also sheet 1,2,3,4,6
Unconnected: IC19.3(A:R) IC19.6(B:R) IC19.10(C:R) IC19.13(D:D) IC19.14(D:R) IC19.15(D:B) IC21.3(B:Y4) IC21.5(B:Y3) IC23.3(B:Y4) IC23.5(B:Y3) IC25.3(B:Y4) IC25.5(B:Y3) IC27.3(B:Y4) IC27.5(B:Y3) IC28.3(A:R) IC28.6(B:R) IC28.10(C:R) IC28.14(D:R) IC29.3(A:R) IC29.6(B:R) IC29.10(C:R) IC29.14(D:R) IC30.3(A:R) IC30.6(B:R) IC30.10(C:R) IC30.14(D:R)

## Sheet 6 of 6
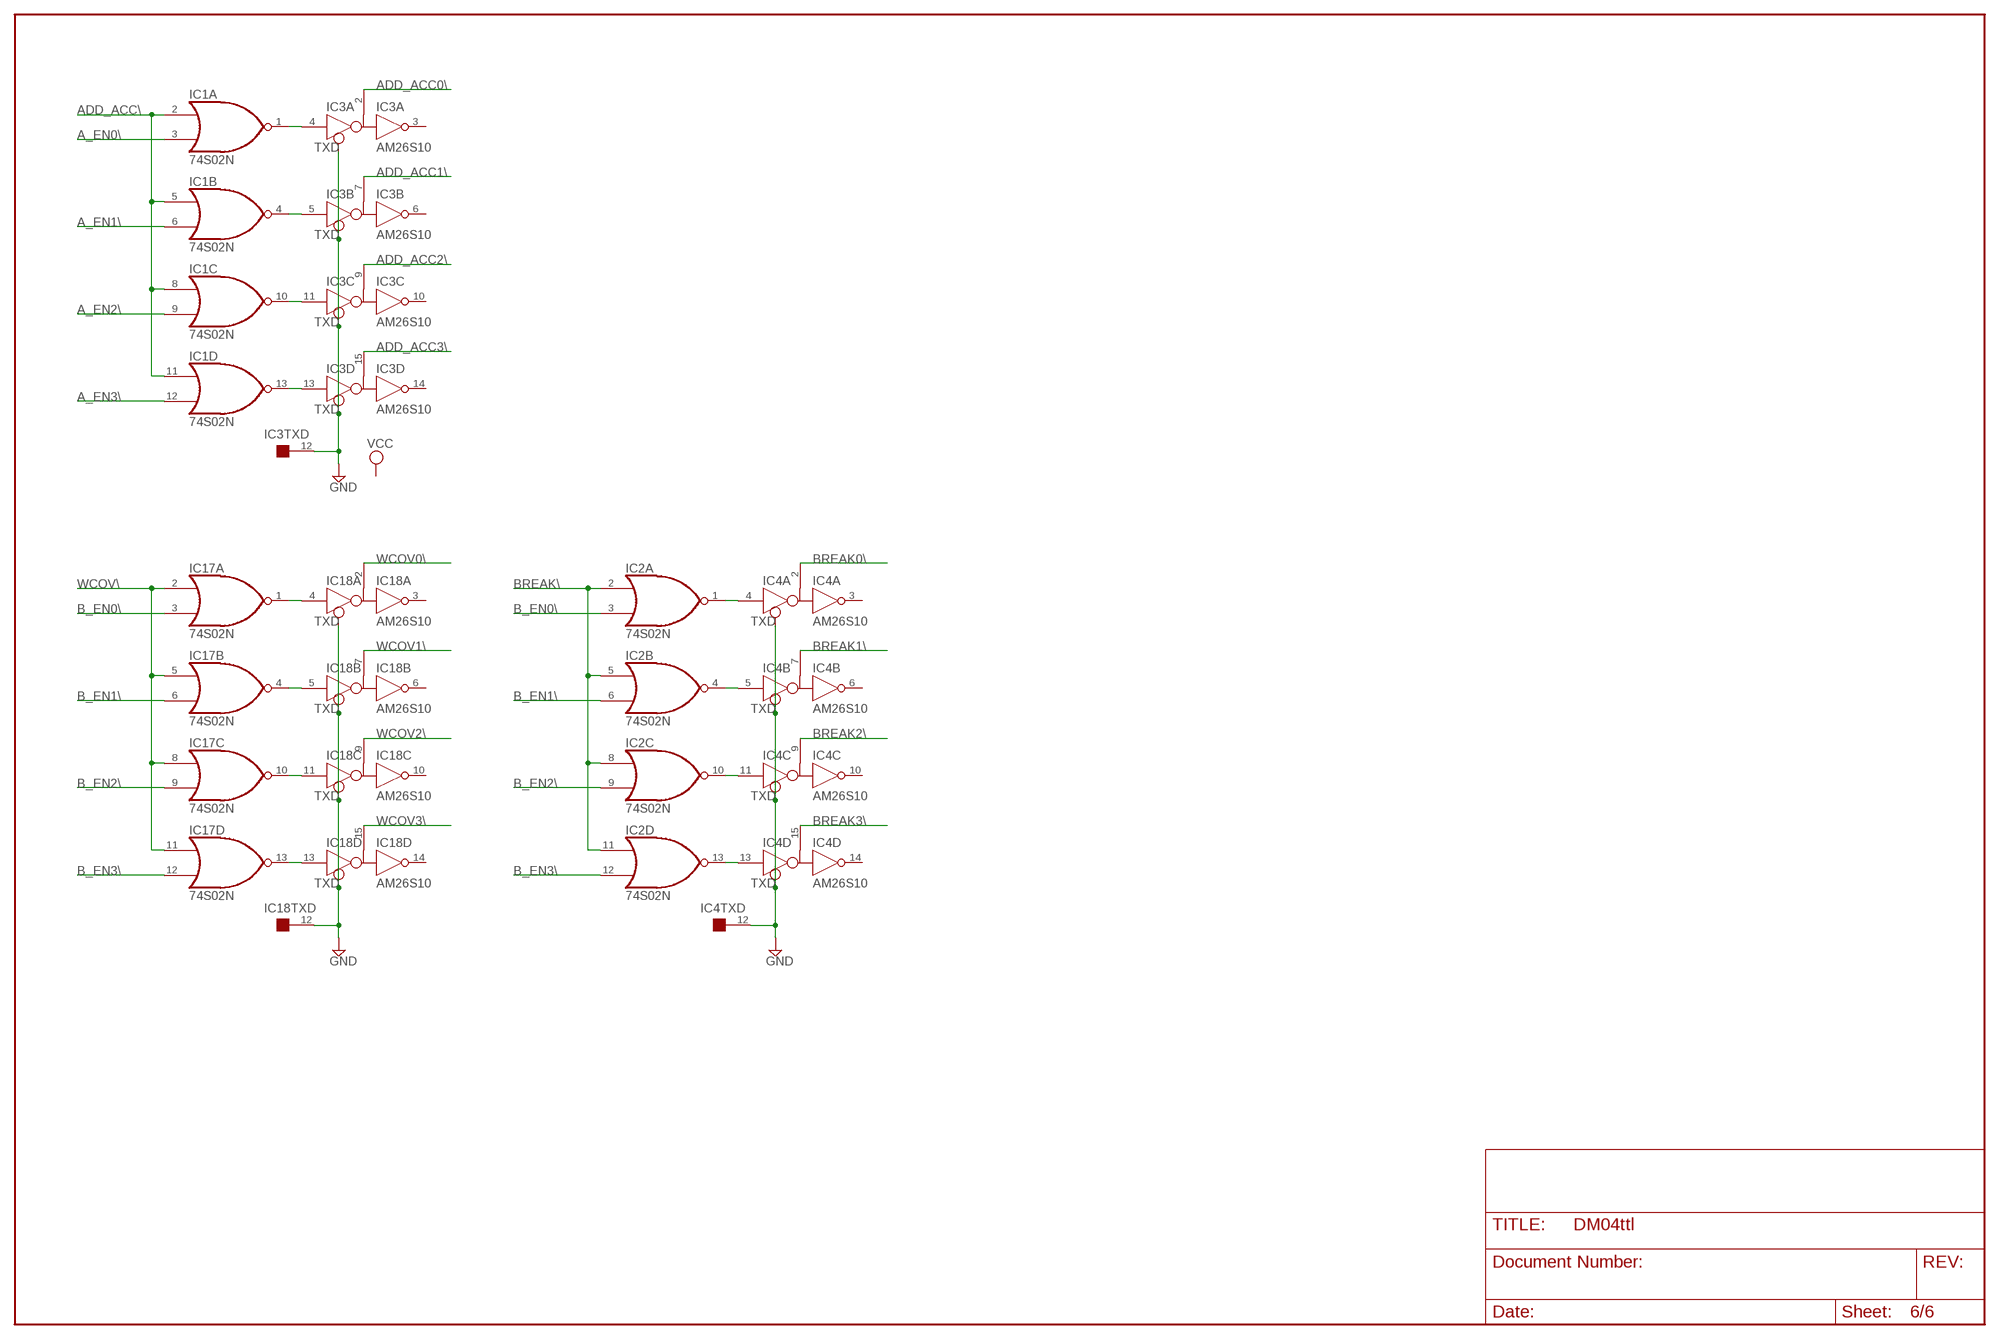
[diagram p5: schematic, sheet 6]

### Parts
IC1  74S02N  [DIL14]
IC2  74S02N  [DIL14]
IC3  AM26S10  [DIL16]
IC4  AM26S10  [DIL16]
IC17  74S02N  [DIL14]
IC18  AM26S10  [DIL16]

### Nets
A_EN0\: IC1.3(A:I1) ; also sheet 1,4
A_EN1\: IC1.6(B:I1) ; also sheet 1,4
A_EN2\: IC1.9(C:I1) ; also sheet 1,4
A_EN3\: IC1.12(D:I1) ; also sheet 1,4
ADD_ACC0\: IC3.2(A:B) ; also sheet 3
ADD_ACC1\: IC3.7(B:B) ; also sheet 3
ADD_ACC2\: IC3.9(C:B) ; also sheet 3
ADD_ACC3\: IC3.15(D:B) ; also sheet 3
ADD_ACC\: IC1.2(A:I0) IC1.5(B:I0) IC1.8(C:I0) IC1.11(D:I0) ; also sheet 1,3
B_EN0\: IC2.3(A:I1) IC17.3(A:I1) ; also sheet 1,5
B_EN1\: IC2.6(B:I1) IC17.6(B:I1) ; also sheet 1,5
B_EN2\: IC2.9(C:I1) IC17.9(C:I1) ; also sheet 1,5
B_EN3\: IC2.12(D:I1) IC17.12(D:I1) ; also sheet 1,5
BREAK0\: IC4.2(A:B) ; also sheet 3
BREAK1\: IC4.7(B:B) ; also sheet 3
BREAK2\: IC4.9(C:B) ; also sheet 3
BREAK3\: IC4.15(D:B) ; also sheet 3
BREAK\: IC2.2(A:I0) IC2.5(B:I0) IC2.8(C:I0) IC2.11(D:I0) ; also sheet 3
GND [Supply]: IC3.12(TXD:TXD) IC4.12(TXD:TXD) IC18.12(TXD:TXD) ; also sheet 1,2,3,4,5
N$4: IC17.1(A:O) IC18.4(A:D)
N$10: IC17.10(C:O) IC18.11(C:D)
N$19: IC17.4(B:O) IC18.5(B:D)
N$21: IC17.13(D:O) IC18.13(D:D)
N$31: IC2.1(A:O) IC4.4(A:D)
N$33: IC2.10(C:O) IC4.11(C:D)
N$34: IC2.4(B:O) IC4.5(B:D)
N$36: IC2.13(D:O) IC4.13(D:D)
N$37: IC1.1(A:O) IC3.4(A:D)
N$38: IC1.10(C:O) IC3.11(C:D)
N$39: IC1.4(B:O) IC3.5(B:D)
N$41: IC1.13(D:O) IC3.13(D:D)
WCOV0\: IC18.2(A:B) ; also sheet 3
WCOV1\: IC18.7(B:B) ; also sheet 3
WCOV2\: IC18.9(C:B) ; also sheet 3
WCOV3\: IC18.15(D:B) ; also sheet 3
WCOV\: IC17.2(A:I0) IC17.5(B:I0) IC17.8(C:I0) IC17.11(D:I0) ; also sheet 3
Unconnected: IC3.3(A:R) IC3.6(B:R) IC3.10(C:R) IC3.14(D:R) IC4.3(A:R) IC4.6(B:R) IC4.10(C:R) IC4.14(D:R) IC18.3(A:R) IC18.6(B:R) IC18.10(C:R) IC18.14(D:R)

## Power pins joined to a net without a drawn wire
GND: AC0.A AC0.AA AC0.B AC0.C AC0.CC AC0.E AC0.EE AC0.H AC0.HH AC0.K AC0.KK AC0.M AC0.MM AC0.P AC0.PP AC0.S AC0.SS AC0.U AC0.UU AC0.VV AC0.W AC0.Y AC1.A AC1.AA AC1.B AC1.C AC1.CC AC1.E AC1.EE AC1.H AC1.HH AC1.K AC1.KK AC1.M AC1.MM AC1.P AC1.PP AC1.S AC1.SS AC1.U AC1.UU AC1.VV AC1.W AC1.Y ADDRESS0.A ADDRESS0.AA ADDRESS0.B ADDRESS0.C ADDRESS0.CC ADDRESS0.E ADDRESS0.EE ADDRESS0.H ADDRESS0.HH ADDRESS0.K ADDRESS0.KK ADDRESS0.M ADDRESS0.MM ADDRESS0.P ADDRESS0.PP ADDRESS0.S ADDRESS0.SS ADDRESS0.U ADDRESS0.UU ADDRESS0.VV ADDRESS0.W ADDRESS0.Y ADDRESS1.A ADDRESS1.AA ADDRESS1.B ADDRESS1.C ADDRESS1.CC ADDRESS1.E ADDRESS1.EE ADDRESS1.H ADDRESS1.HH ADDRESS1.K ADDRESS1.KK ADDRESS1.M ADDRESS1.MM ADDRESS1.P ADDRESS1.PP ADDRESS1.S ADDRESS1.SS ADDRESS1.U ADDRESS1.UU ADDRESS1.VV ADDRESS1.W ADDRESS1.Y ADDRESS2.A ADDRESS2.AA ADDRESS2.B ADDRESS2.C ADDRESS2.CC ADDRESS2.E ADDRESS2.EE ADDRESS2.H ADDRESS2.HH ADDRESS2.K ADDRESS2.KK ADDRESS2.M ADDRESS2.MM ADDRESS2.P ADDRESS2.PP ADDRESS2.S ADDRESS2.SS ADDRESS2.U ADDRESS2.UU ADDRESS2.VV ADDRESS2.W ADDRESS2.Y ADDRESS3.A ADDRESS3.AA ADDRESS3.B ADDRESS3.C ADDRESS3.CC ADDRESS3.E ADDRESS3.EE ADDRESS3.H ADDRESS3.HH ADDRESS3.K ADDRESS3.KK ADDRESS3.M ADDRESS3.MM ADDRESS3.P ADDRESS3.PP ADDRESS3.S ADDRESS3.SS ADDRESS3.U ADDRESS3.UU ADDRESS3.VV ADDRESS3.W ADDRESS3.Y ADDRESS.A ADDRESS.AA ADDRESS.B ADDRESS.C ADDRESS.CC ADDRESS.E ADDRESS.EE ADDRESS.H ADDRESS.HH ADDRESS.K ADDRESS.KK ADDRESS.M ADDRESS.MM ADDRESS.P ADDRESS.PP ADDRESS.S ADDRESS.SS ADDRESS.U ADDRESS.UU ADDRESS.VV ADDRESS.W ADDRESS.Y BAC0.A BAC0.AA BAC0.B BAC0.C BAC0.CC BAC0.E BAC0.EE BAC0.H BAC0.HH BAC0.K BAC0.KK BAC0.M BAC0.MM BAC0.P BAC0.PP BAC0.S BAC0.SS BAC0.U BAC0.UU BAC0.VV BAC0.W BAC0.Y BAC1.A BAC1.AA BAC1.B BAC1.C BAC1.CC BAC1.E BAC1.EE BAC1.H BAC1.HH BAC1.K BAC1.KK BAC1.M BAC1.MM BAC1.P BAC1.PP BAC1.S BAC1.SS BAC1.U BAC1.UU BAC1.VV BAC1.W BAC1.Y BMB0.A BMB0.AA BMB0.B BMB0.C BMB0.CC BMB0.E BMB0.EE BMB0.H BMB0.HH BMB0.K BMB0.KK BMB0.M BMB0.MM BMB0.P BMB0.PP BMB0.S BMB0.SS BMB0.U BMB0.UU BMB0.VV BMB0.W BMB0.Y BMB1.A BMB1.AA BMB1.B BMB1.C BMB1.CC BMB1.E BMB1.EE BMB1.H BMB1.HH BMB1.K BMB1.KK BMB1.M BMB1.MM BMB1.P BMB1.PP BMB1.S BMB1.SS BMB1.U BMB1.UU BMB1.VV BMB1.W BMB1.Y DATA0.A DATA0.AA DATA0.B DATA0.C DATA0.CC DATA0.E DATA0.EE DATA0.H DATA0.HH DATA0.K DATA0.KK DATA0.M DATA0.MM DATA0.P DATA0.PP DATA0.S DATA0.SS DATA0.U DATA0.UU DATA0.VV DATA0.W DATA0.Y DATA1.A DATA1.AA DATA1.B DATA1.C DATA1.CC DATA1.E DATA1.EE DATA1.H DATA1.HH DATA1.K DATA1.KK DATA1.M DATA1.MM DATA1.P DATA1.PP DATA1.S DATA1.SS DATA1.U DATA1.UU DATA1.VV DATA1.W DATA1.Y DATA2.A DATA2.AA DATA2.B DATA2.C DATA2.CC DATA2.E DATA2.EE DATA2.H DATA2.HH DATA2.K DATA2.KK DATA2.M DATA2.MM DATA2.P DATA2.PP DATA2.S DATA2.SS DATA2.U DATA2.UU DATA2.VV DATA2.W DATA2.Y DATA3.A DATA3.AA DATA3.B DATA3.C DATA3.CC DATA3.E DATA3.EE DATA3.H DATA3.HH DATA3.K DATA3.KK DATA3.M DATA3.MM DATA3.P DATA3.PP DATA3.S DATA3.SS DATA3.U DATA3.UU DATA3.VV DATA3.W DATA3.Y DATA.A DATA.AA DATA.B DATA.C DATA.CC DATA.E DATA.EE DATA.H DATA.HH DATA.K DATA.KK DATA.M DATA.MM DATA.P DATA.PP DATA.S DATA.SS DATA.U DATA.UU DATA.VV DATA.W DATA.Y IC1.7(P:GND) IC2.7(P:GND) IC3.1(GND:GND) IC3.8(PWR:GND) IC4.1(GND:GND) IC4.8(PWR:GND) IC5.1(GND:GND) IC5.8(PWR:GND) IC6.10(P:GND) IC7.10(P:GND) IC8.10(P:GND) IC9.10(P:GND) IC10.10(P:GND) IC11.10(P:GND) IC12.10(P:GND) IC13.10(P:GND) IC14.1(GND:GND) IC14.8(PWR:GND) IC15.1(GND:GND) IC15.8(PWR:GND) IC16.1(GND:GND) IC16.8(PWR:GND) IC17.7(P:GND) IC18.1(GND:GND) IC18.8(PWR:GND) IC19.1(GND:GND) IC19.8(PWR:GND) IC20.10(P:GND) IC21.10(P:GND) IC22.10(P:GND) IC23.10(P:GND) IC24.10(P:GND) IC25.10(P:GND) IC26.10(P:GND) IC27.10(P:GND) IC28.1(GND:GND) IC28.8(PWR:GND) IC29.1(GND:GND) IC29.8(PWR:GND) IC30.1(GND:GND) IC30.8(PWR:GND) IC31.8(GND) IC32.8(GND) IC33.10(GND) IC34.7(P:GND) IC35.10(GND)
VCC: IC1.14(P:VCC) IC2.14(P:VCC) IC3.16(PWR:VCC) IC4.16(PWR:VCC) IC5.16(PWR:VCC) IC6.20(P:VCC) IC7.20(P:VCC) IC8.20(P:VCC) IC9.20(P:VCC) IC10.20(P:VCC) IC11.20(P:VCC) IC12.20(P:VCC) IC13.20(P:VCC) IC14.16(PWR:VCC) IC15.16(PWR:VCC) IC16.16(PWR:VCC) IC17.14(P:VCC) IC18.16(PWR:VCC) IC19.16(PWR:VCC) IC20.20(P:VCC) IC21.20(P:VCC) IC22.20(P:VCC) IC23.20(P:VCC) IC24.20(P:VCC) IC25.20(P:VCC) IC26.20(P:VCC) IC27.20(P:VCC) IC28.16(PWR:VCC) IC29.16(PWR:VCC) IC30.16(PWR:VCC) IC31.16(VCC) IC32.16(VCC) IC33.20(VCC) IC34.14(P:VCC) IC35.20(VCC)

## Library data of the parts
AC0 AC1 ADDRESS ADDRESS0 ADDRESS1-ADDRESS3 BAC0 BAC1 BMB0 BMB1 DATA DATA0 DATA1-DATA3 = dec-con:BC08J: BC08J compatible bus connector
C1-C38 = rcl:C-US: CAPACITOR, American symbol
C96-C99 = rcl:CPOL-US: POLARIZED CAPACITOR, American symbol
E1-E3 = ic-package:DIL20: Dual In Line
IC1 IC2 IC17 = 74xx-jameco:74*02: Quad 2-input NOR gate
IC3-IC5 IC14-IC16 IC18 IC19 IC28-IC30 = dec-con:AM26S10: Bus Transceiver
IC6-IC13 IC20-IC27 = 74xx-jameco:74*240: Octal BUFFER and LINE DRIVER, 3-state
IC31 = 74xx-jameco:74*148: 10-line to 4-line and 8-line to 3-line PRIORITY ENCODER
IC32 = 74xx-jameco:74*138: 3-line to 8-line DECODER/DEMULTIPLEXER
IC33 IC35 = 74xx-jameco:74*273: Octal D type FLIP FLOP, clear
IC34 = 74xx-jameco:74*86: Quad 2-input EXCLUSIV-OR (XOR) gate
RN1 RN2 RN5-RN10 RN13-RN20 = resistor-sil:GE09R: SIL RESISTOR
SV1 = con-lstb:MA10-2: PIN HEADER

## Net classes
1 Supply: width 0.635 mm, drill 0.381 mm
